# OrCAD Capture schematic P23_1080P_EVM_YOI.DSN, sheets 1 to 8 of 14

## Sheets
1 P10: DLPA2005: size D
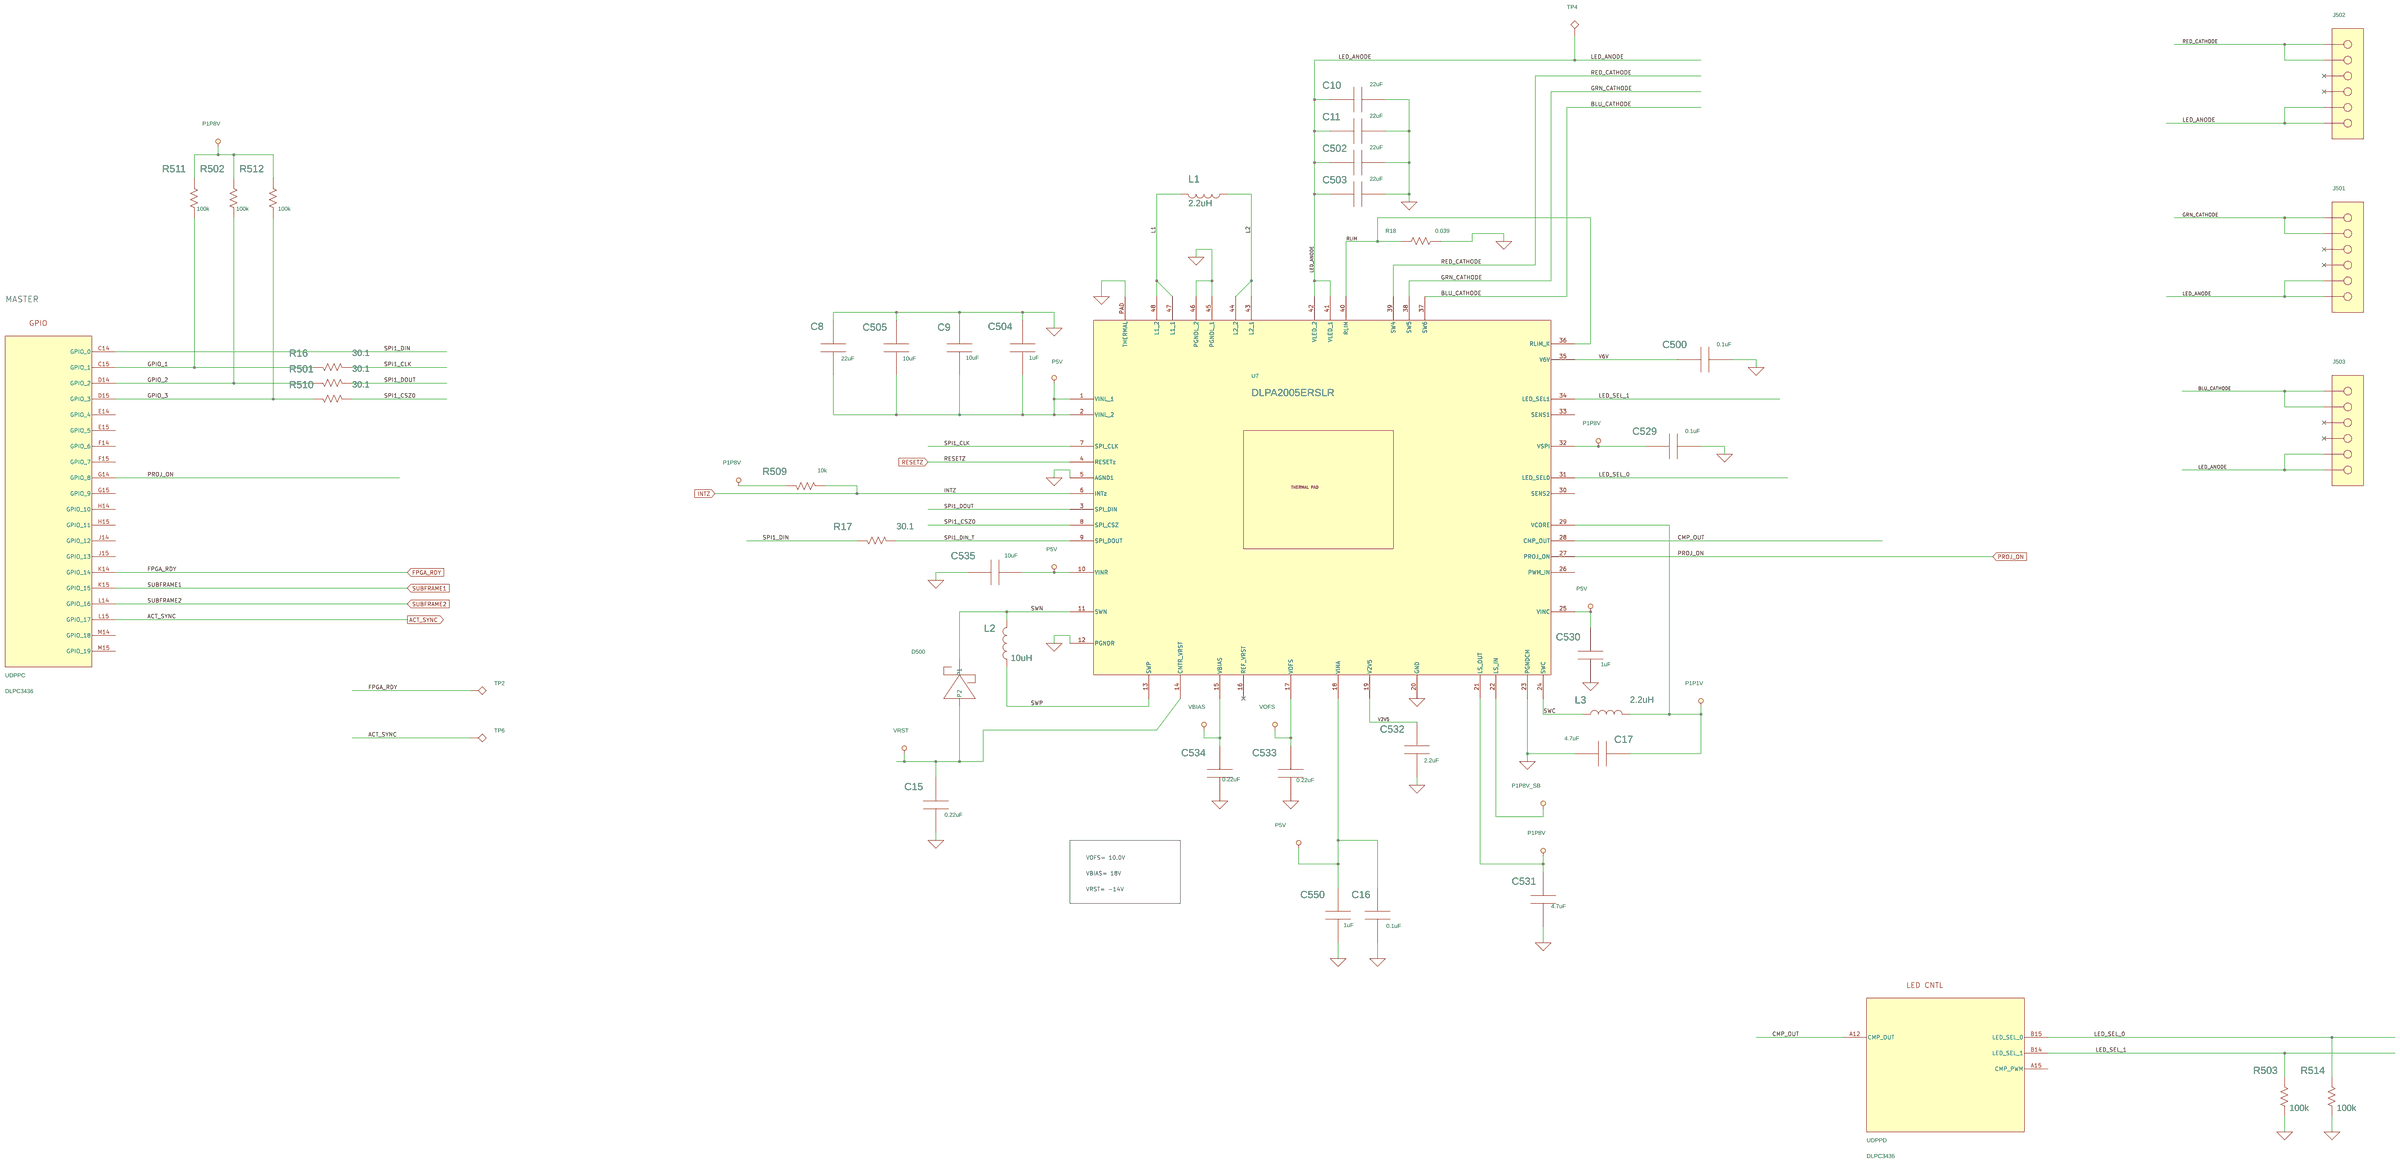
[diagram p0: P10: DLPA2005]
2 P11: Power: size D
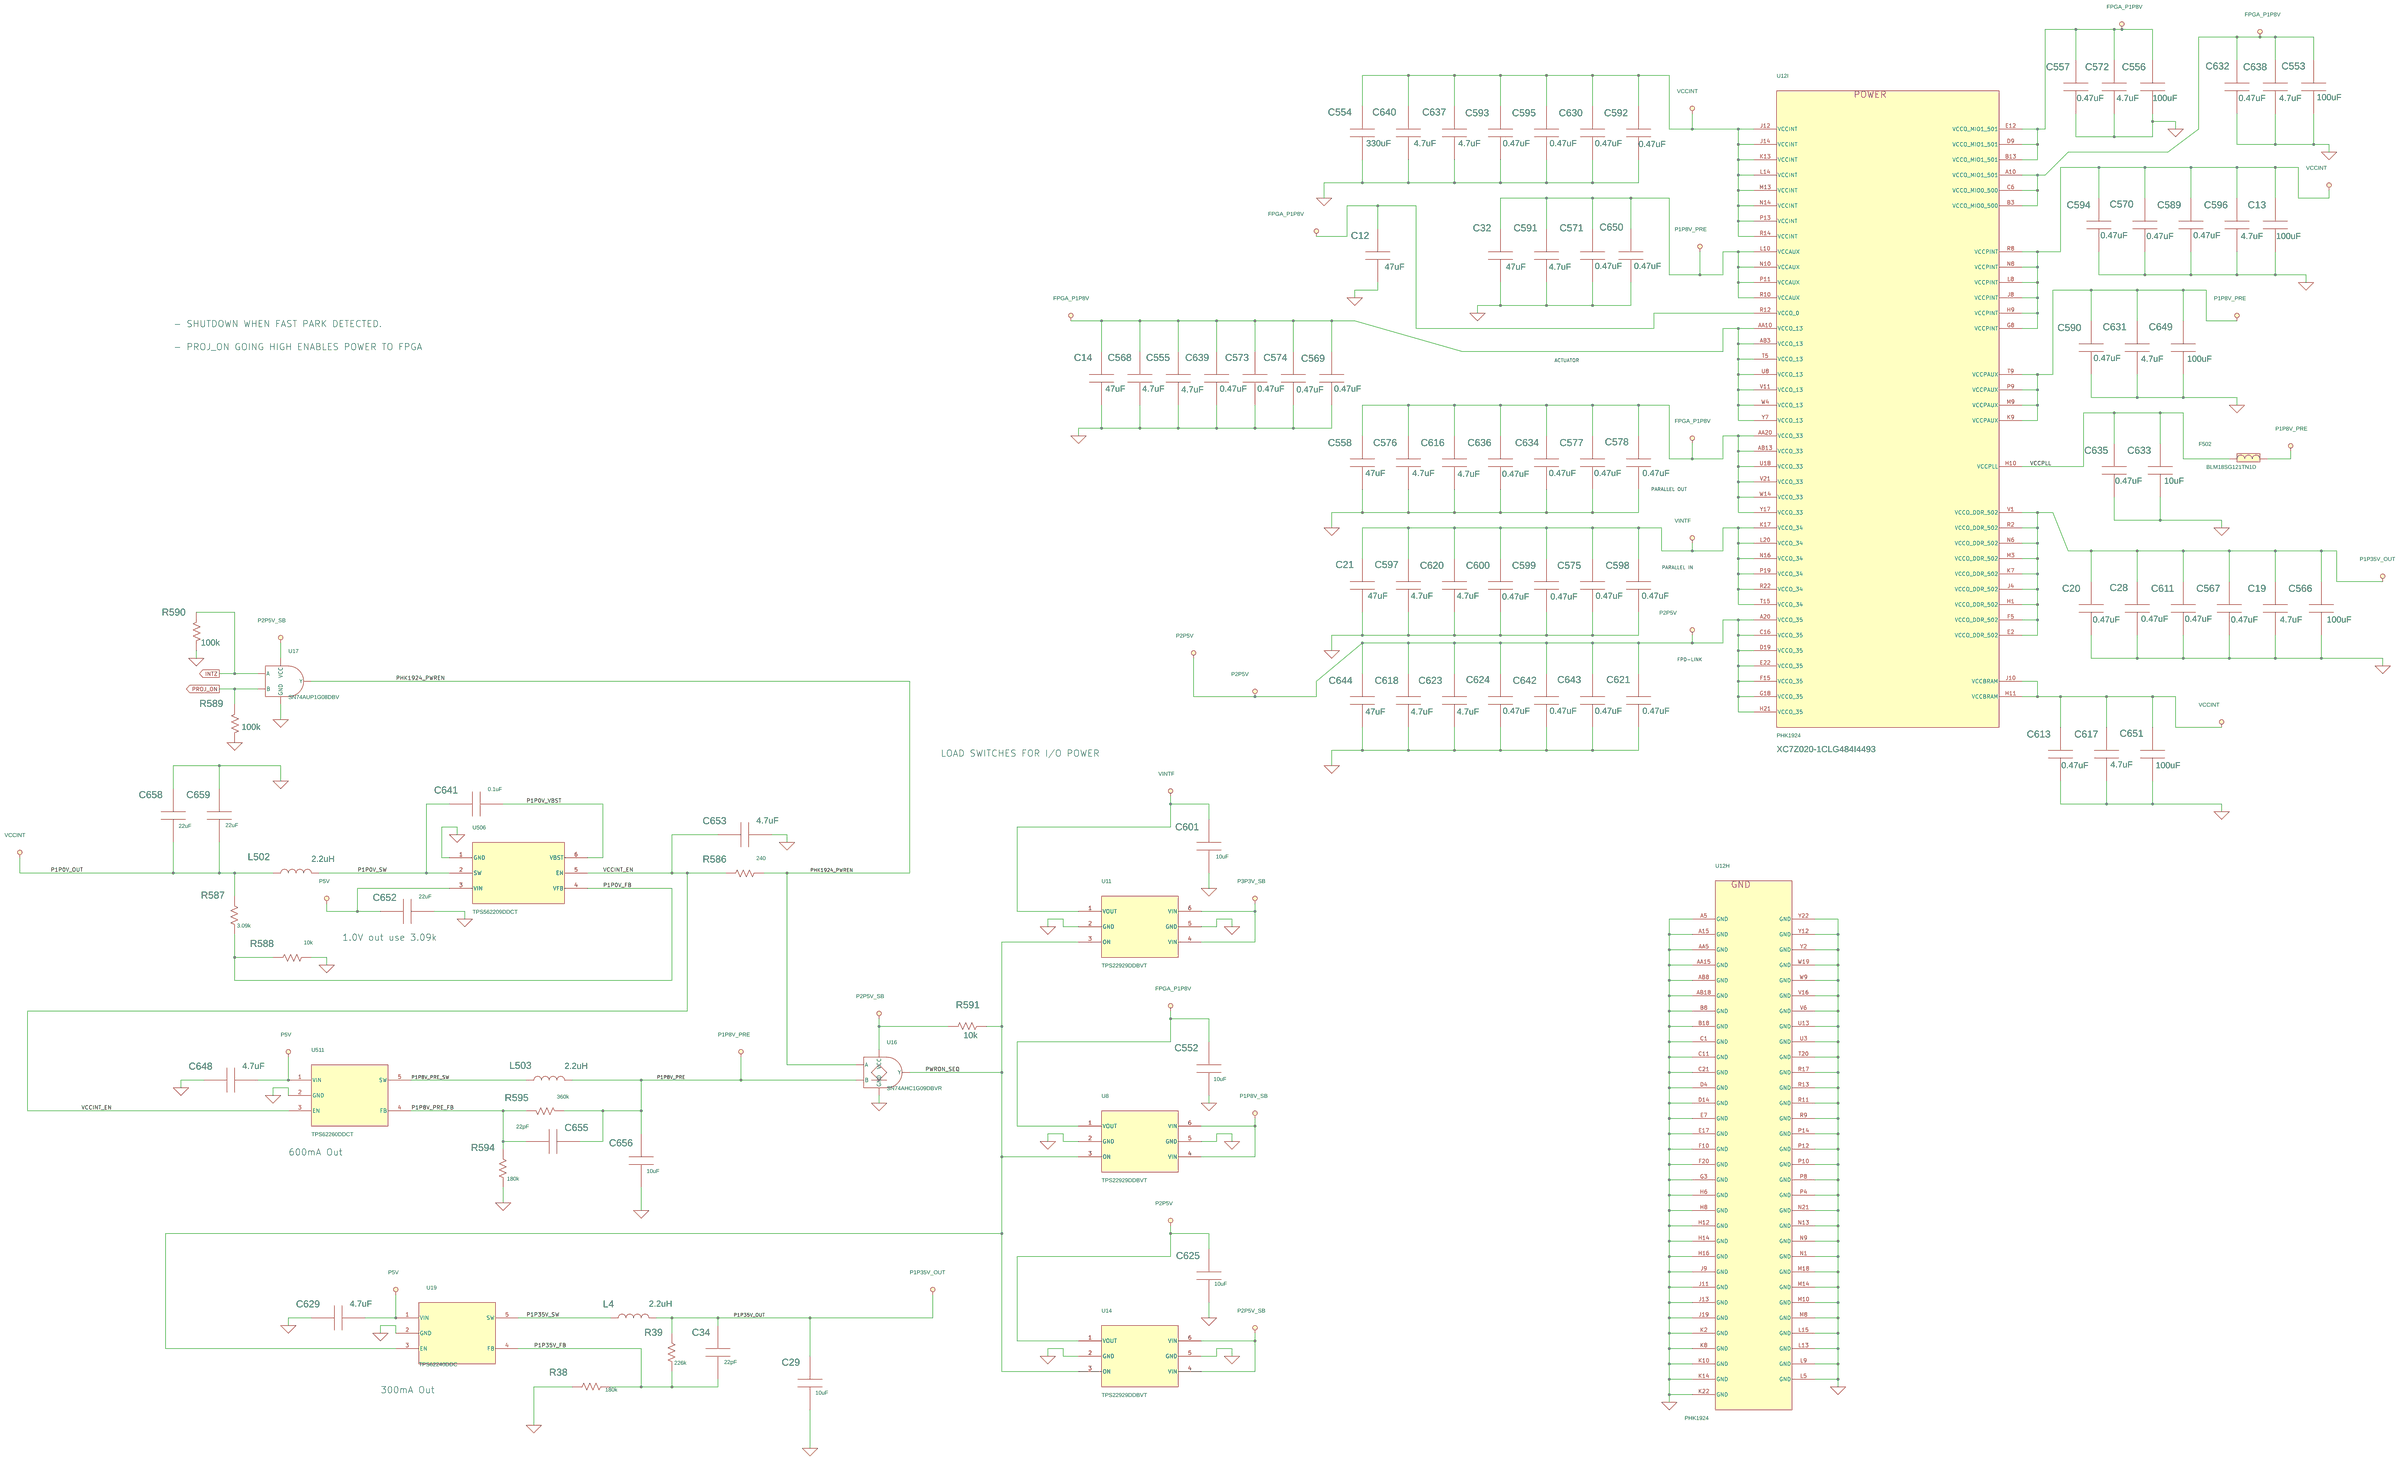
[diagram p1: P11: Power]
3 P14: Disclaimer
4 P03: DLPC3436 & Flash: size D
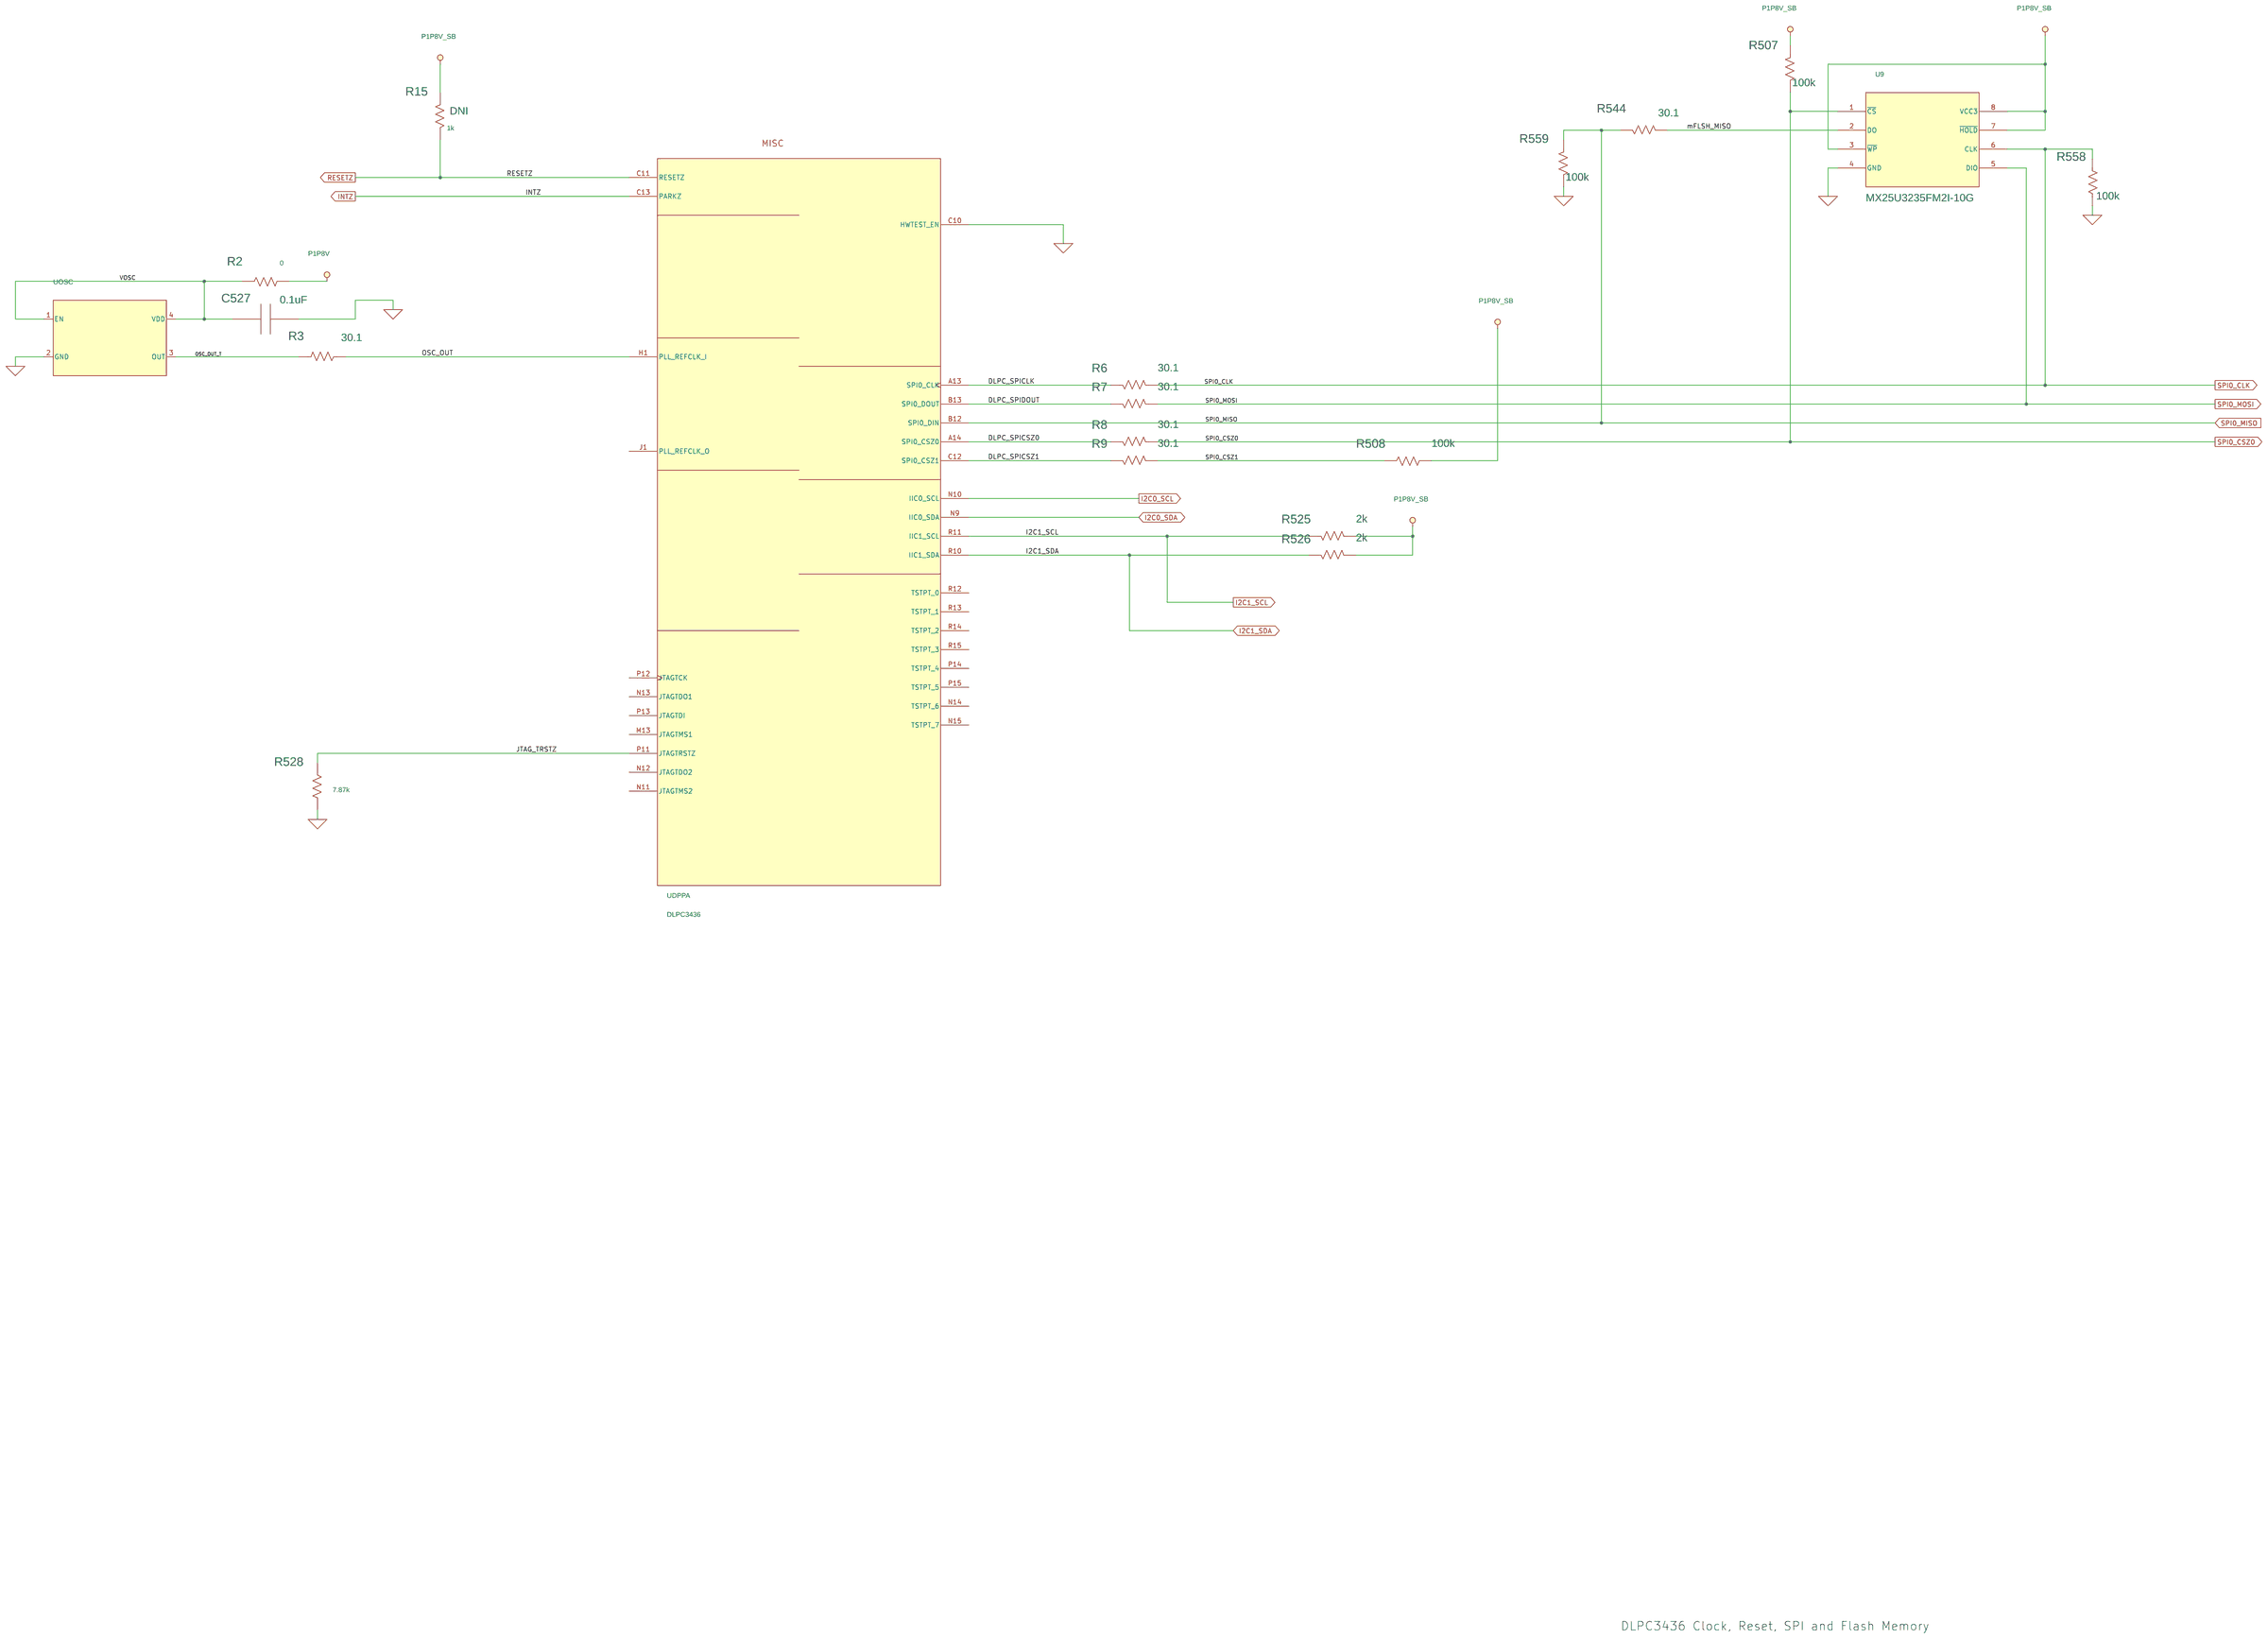
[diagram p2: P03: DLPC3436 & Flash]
5 P01: DLPDLCR230NPEVM: title: TIDA-080009 DLPDLCR230NPEVM; rev: A; company: Texas Instruments Inc.
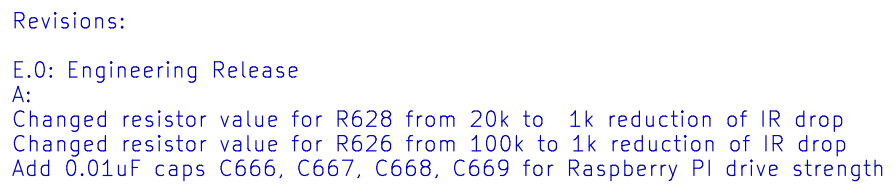
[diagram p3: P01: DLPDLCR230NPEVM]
6 P07: DLPC3436 Power: size D
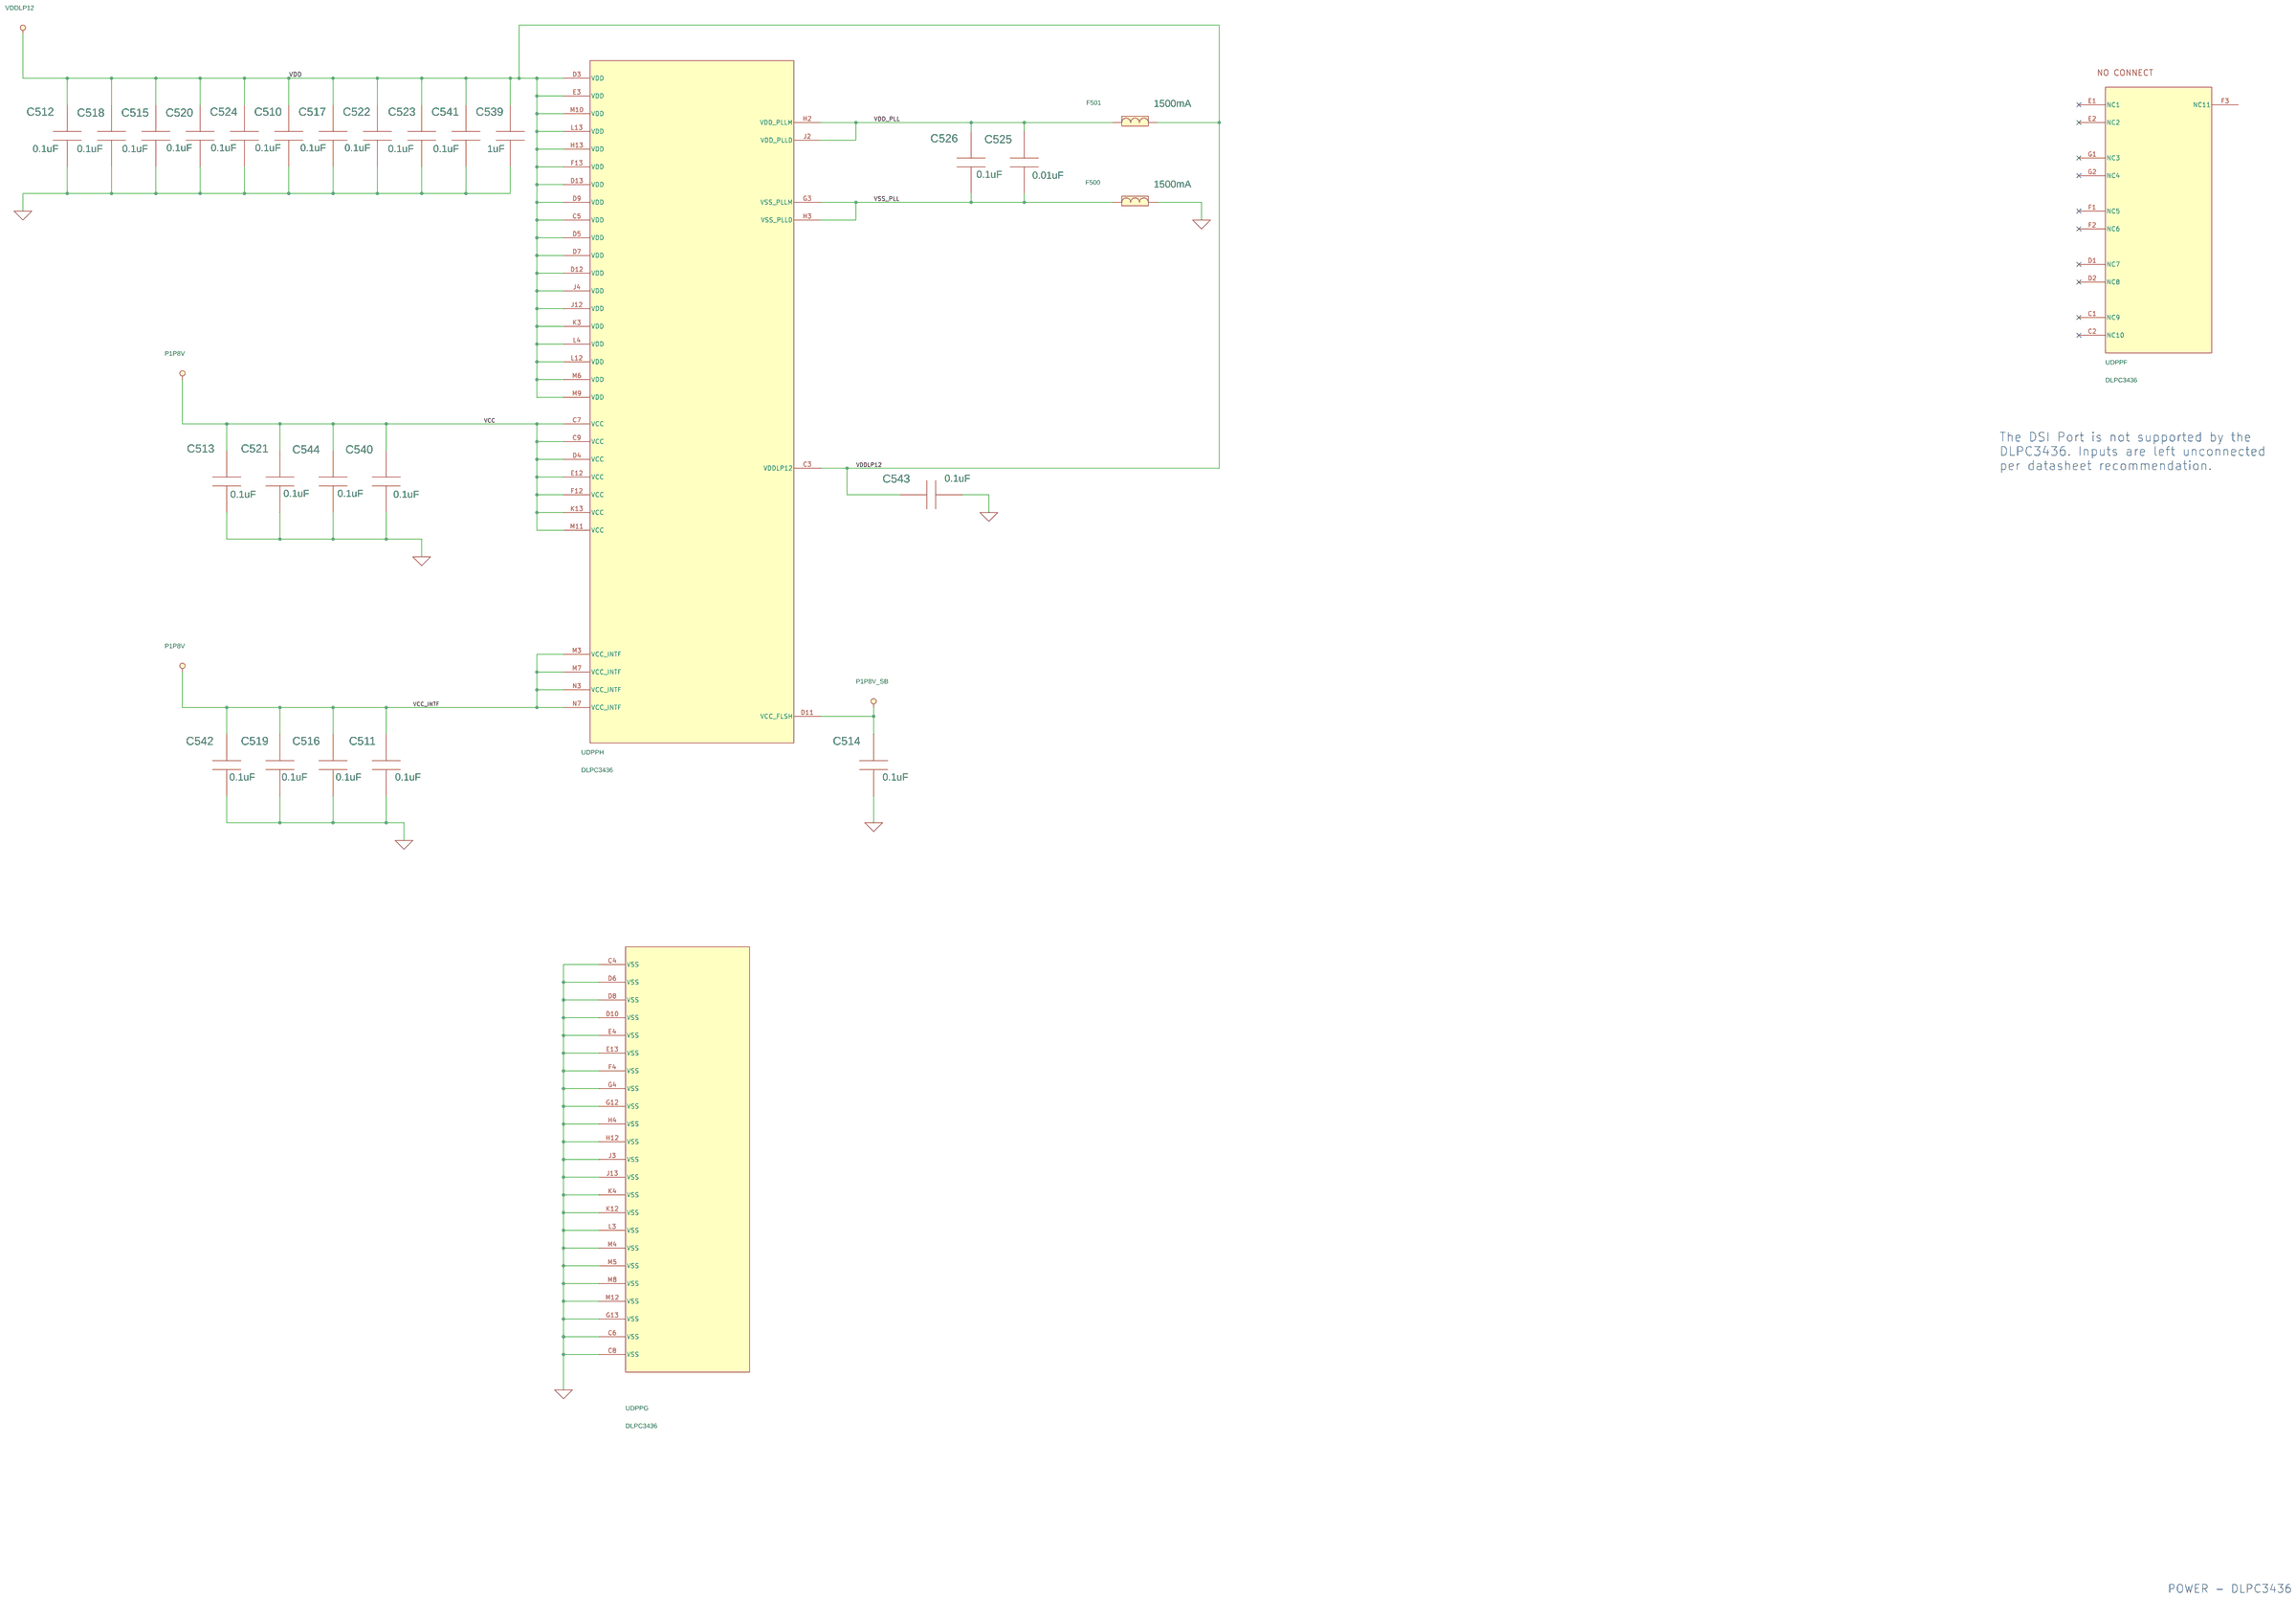
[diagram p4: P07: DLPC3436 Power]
7 P12: Actuator Driver: size D
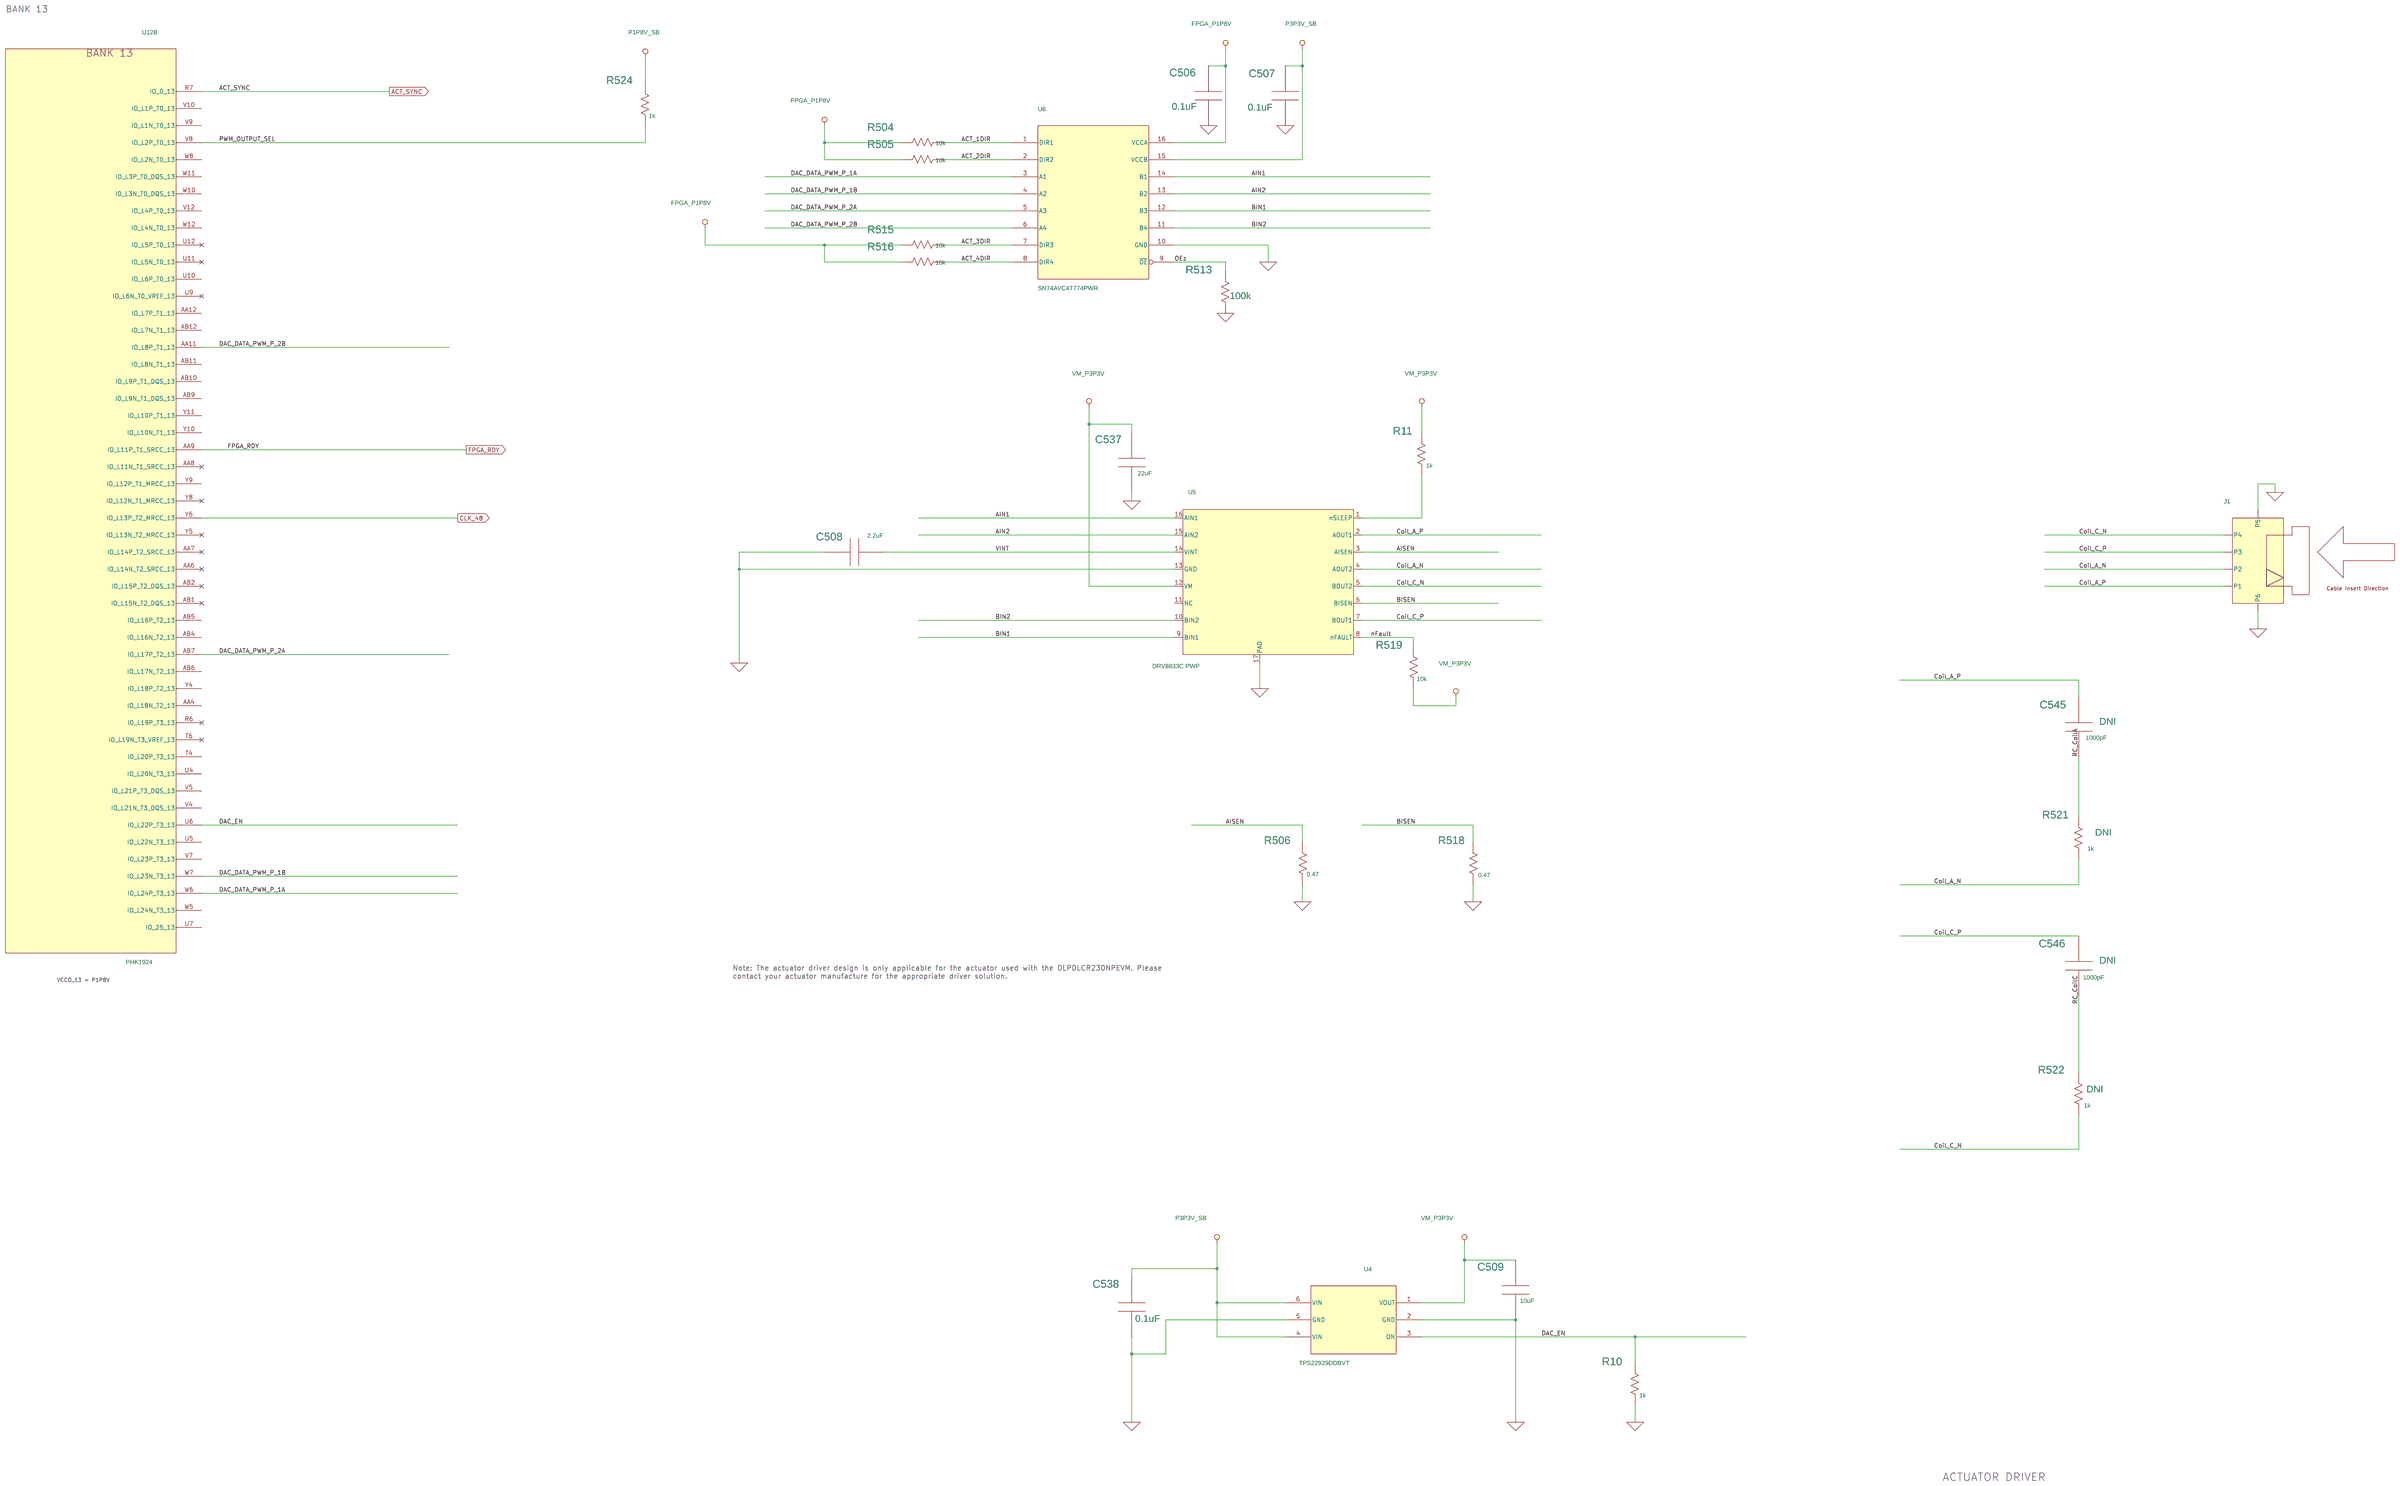
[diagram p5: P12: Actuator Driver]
8 P05: FPD-Link Video Input: size D
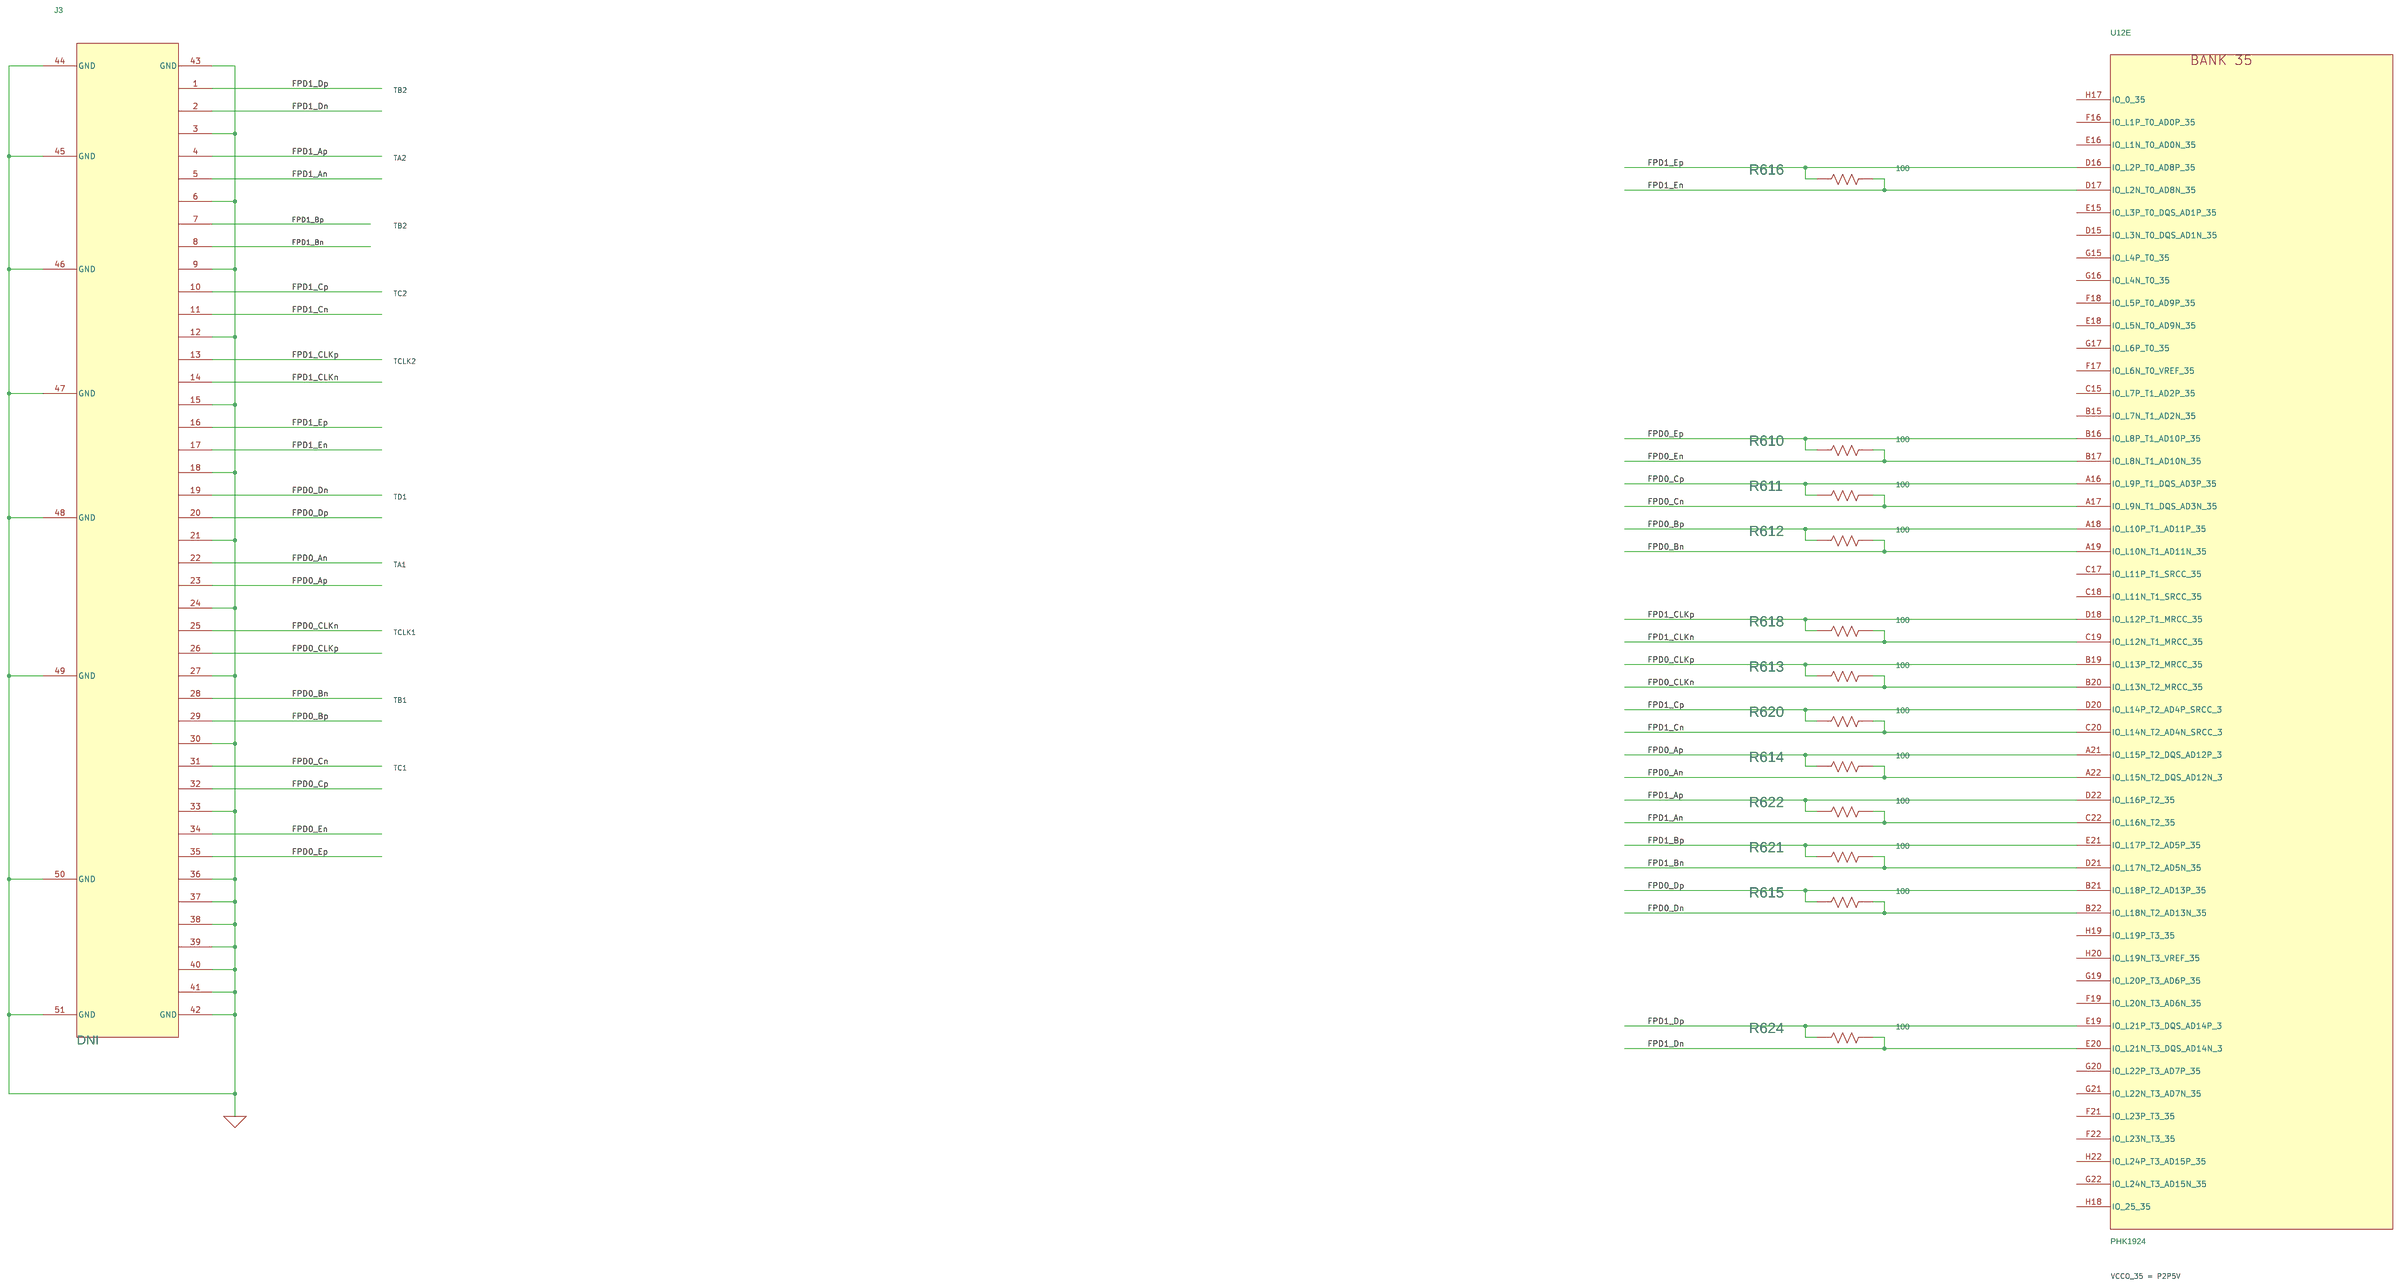
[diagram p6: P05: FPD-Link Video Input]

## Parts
sheet P03: DLPC3436 & Flash
C527  0.1uF  [0402_AVXA]
R2  0  [0402]
R3  30.1  [0402]
R6  30.1  [0402]
R7  30.1  [0402]
R8  30.1  [0402]
R9  30.1  [0402]
R15  1k  [0402]
R507  100k  [0402]
R508  100k  [0402]
R525  2k  [0402]
R526  2k  [0402]
R528  7.87k  [0402]
R544  30.1  [0402]
R558  100k  [0402]
R559  100k  [0402]
U9  MX25U3235FM2I-10G  [SOIC-8_208mil]
UOSC  24MHz  [ECS-2018_2p5mmx2mm]
sheet P05: FPD-Link Video Input
J3  EM,CONN,FI-RE41S-VF  [FI-RE41S-VF_JAE]
R610  100  [0402]
R611  100  [0402]
R612  100  [0402]
R613  100  [0402]
R614  100  [0402]
R615  100  [0402]
R616  100  [0402]
R618  100  [0402]
R620  100  [0402]
R621  100  [0402]
R622  100  [0402]
R624  100  [0402]
sheet P07: DLPC3436 Power
C510  0.1uF  [0402_AVXA]
C511  0.1uF  [0402_AVXA]
C512  0.1uF  [0402_AVXA]
C513  0.1uF  [0402_AVXA]
C514  0.1uF  [0402_AVXA]
C515  0.1uF  [0402_AVXA]
C516  0.1uF  [0402_AVXA]
C517  0.1uF  [0402_AVXA]
C518  0.1uF  [0402_AVXA]
C519  0.1uF  [0402_AVXA]
C520  0.1uF  [0402_AVXA]
C521  0.1uF  [0402_AVXA]
C522  0.1uF  [0402_AVXA]
C523  0.1uF  [0402_AVXA]
C524  0.1uF  [0402_AVXA]
C525  0.01uF  [0402]
C526  0.1uF  [0402_AVXA]
C539  1uF  [0402]
C540  0.1uF  [0402_AVXA]
C541  0.1uF  [0402_AVXA]
C542  0.1uF  [0402_AVXA]
C543  0.1uF  [0402_AVXA]
C544  0.1uF  [0402_AVXA]
F500  BLM15PD800SN1D  [BLM15P]
F501  BLM15PD800SN1D  [BLM15P]
sheet P08: Frame Buffer Memory
U12  PHK1924  [Xilinx_CLG484]  (sections A,B,C,D,E,F,G,H,I,J)
sheet P10: DLPA2005
C8  22uF  [0603]
C9  10uF  [0603]
C10  22uF  [0603]
C11  22uF  [0603]
C15  0.22uF  [0402]
C16  0.1uF  [0402_AVXA]
C17  4.7uF  [0402]
C500  0.1uF  [0402_AVXA]
C502  22uF  [0603]
C503  22uF  [0603]
C504  1uF  [0402]
C505  10uF  [0603]
C529  0.1uF  [0402_AVXA]
C530  1uF  [0402]
C531  4.7uF  [0402]
C532  2.2uF  [0402]
C533  0.22uF  [0402]
C534  0.22uF  [0402]
C535  10uF  [0603]
C550  1uF  [0402]
D500  PMEG4002EL  [SOD882]
J501  SM06B-SRSS-TB(LF)(SN)  [CONN6_SM06B_SH_JST]
J502  SM06B-SRSS-TB(LF)(SN)  [CONN6_SM06B_SH_JST]
J503  SM06B-SRSS-TB(LF)(SN)  [CONN6_SM06B_SH_JST]
L1  2.2uH  [CooperBussmann_DR74]
L2  10uH  [0805]
L3  2.2uH  [1008_2p5mmx2mm]
R16  30.1  [0402]
R17  30.1  [0402]
R18  0.039  [0603]
R501  30.1  [0402]
R502  100k  [0402]
R503  100k  [0402]
R509  10k  [0402]
R510  30.1  [0402]
R511  100k  [0402]
R512  100k  [0402]
R514  100k  [0402]
TP2  TP40  [TP40]
TP4  TP40  [TP40]
TP6  TP40  [TP40]
U7  DLPA2005  [PAD2005_RSL_S-PQFP-N48_QFN48]
UDPP  DLPC3436  [DPP3433_7mmx7mm_VFBGA_176balls]  (sections A,B,C,D,E,F,G,H)
sheet P11: Power
C12  47uF  [0805]
C13  100uF  [0805]
C14  47uF  [0805]
C19  4.7uF  [0402]
C20  0.47uF  [0402]
C21  47uF  [0805]
C28  0.47uF  [0402]
C29  10uF  [0603]
C32  47uF  [0805]
C34  22pF  [0402]
C552  10uF  [0603]
C553  100uF  [0805]
C554  330uF  [1210]
C555  4.7uF  [0402]
C556  100uF  [0805]
C557  0.47uF  [0402]
C558  47uF  [0805]
C566  100uF  [0805]
C567  0.47uF  [0402]
C568  4.7uF  [0402]
C569  0.47uF  [0402]
C570  0.47uF  [0402]
C571  0.47uF  [0402]
C572  4.7uF  [0402]
C573  0.47uF  [0402]
C574  0.47uF  [0402]
C575  0.47uF  [0402]
C576  4.7uF  [0402]
C577  0.47uF  [0402]
C578  0.47uF  [0402]
C589  0.47uF  [0402]
C590  0.47uF  [0402]
C591  4.7uF  [0402]
C592  0.47uF  [0402]
C593  0.47uF  [0402]
C594  0.47uF  [0402]
C595  0.47uF  [0402]
C596  4.7uF  [0402]
C597  4.7uF  [0402]
C598  0.47uF  [0402]
C599  0.47uF  [0402]
C600  0.47uF  [0402]
C601  10uF  [0603]
C611  0.47uF  [0402]
C613  0.47uF  [0402]
C616  4.7uF  [0402]
C617  4.7uF  [0402]
C618  4.7uF  [0402]
C620  4.7uF  [0402]
C621  0.47uF  [0402]
C623  4.7uF  [0402]
C624  0.47uF  [0402]
C625  10uF  [0603]
C629  4.7uF  [0402]
C630  0.47uF  [0402]
C631  4.7uF  [0402]
C632  0.47uF  [0402]
C633  10uF  [0603]
C634  0.47uF  [0402]
C635  0.47uF  [0402]
C636  0.47uF  [0402]
C637  4.7uF  [0402]
C638  4.7uF  [0402]
C639  0.47uF  [0402]
C640  4.7uF  [0402]
C641  0.1uF  [0402_AVXA]
C642  0.47uF  [0402]
C643  0.47uF  [0402]
C644  47uF  [0805]
C648  4.7uF  [0402]
C649  100uF  [0805]
C650  0.47uF  [0402]
C651  100uF  [0805]
C652  22uF  [0603]
C653  4.7uF  [0402]
C655  22pF  [0402]
C656  10uF  [0603]
C658  22uF  [0603]
C659  22uF  [0603]
F502  BLM18SG121TN1D  [0603]
L4  2.2uH  [1008_2p5mmx2mm]
L502  2.2uH  [XFL4020-Series]
L503  2.2uH  [1008_2p5mmx2mm]
R38  180k  [0402]
R39  226k  [0402]
R586  240  [0402]
R587  3.09k  [0402]
R588  10k  [0402]
R589  100k  [0402]
R590  100k  [0402]
R591  10k  [0402]
R594  180k  [0402]
R595  360k  [0402]
U8  TPS22929DDBVT  [SOT23-6_DBV_R-PDSO-G6]
U11  TPS22929DDBVT  [SOT23-6_DBV_R-PDSO-G6]
U14  TPS22929DDBVT  [SOT23-6_DBV_R-PDSO-G6]
U16  SN74AHC1G09DBVR  [SC70_DBV_R-PDSO-G5]
U17  SN74AUP1G08DBV  [SC70_DBV_R-PDSO-G5]
U19  TPS62240DDC  [TSOT-23_DDC_R-PDSO-G5]
U506  TPS562209DDCT  [SOT-23_DDC_R-PDSO-G6]
U511  TPS62260DDCT  [TSOT-23_DDC_R-PDSO-G5]
sheet P12: Actuator Driver
C506  0.1uF  [0402_AVXA]
C507  0.1uF  [0402_AVXA]
C508  2.2uF  [0402]
C509  10uF  [0603]
C537  22uF  [0603]
C538  0.1uF  [0402_AVXA]
C545  1000pF  [0603]
C546  1000pF  [0603]
J1  5034800400  [Molex_5034800400_2GPADS]
R10  1k  [0402]
R11  1k  [0402]
R504  10k  [0402]
R505  10k  [0402]
R506  0.47  [0603]
R513  100k  [0402]
R515  10k  [0402]
R516  10k  [0402]
R518  0.47  [0603]
R519  10k  [0402]
R521  1k  [0402]
R522  1k  [0402]
R524  1k  [0402]
U4  TPS22929DDBVT  [SOT23-6_DBV_R-PDSO-G6]
U5  DRV8833C PWP  [16-HTSSOP]
U6  SN74AVC4T774PWR  [TSSOP16_PW]

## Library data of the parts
C506 C507 C510-C524 C526 C527 C538 C540-C544 C641 = PAS,CAP,NP,large: DigiKey: 490-7998-1-ND; DigiReel: 490-7998-6-ND; Family: passive; Lead Style: SMT; MFG: Murata; Material: x7r; P/D_NUM: GCM155R71C104KA55J; Part Number: GCM155R71C104KA55J; Part Specific: CAP CER .1UF 16V X7R 0402; TOLERANCE: 10%; Type: capacitor; VENDOR: Murata; VPC: 16V
R2 = PAS,R,large: DigiKey: P0.0JCT-ND; DigiReel: P0.0JDKR-ND; Family: passive; Index PN: 687; Lead Style: SMT; MFG: Panasonic; Material: chip; P/D_NUM: ERJ-2GE0R00X; Part Number: ERJ-2GE0R00X; Part Specific: RES 0.0 OHM 1/16W 0402 SMD; Power: 1/16W; Type: resistor; VENDOR: Panasonic; VPC: 1/16W
R3 R6-R9 R16 R17 R501 R510 R544 = PAS,R,large: DigiKey: YAG3111CT-ND; DigiReel: P30.1LDKR-ND; Family: passive; Index PN: 976; Lead Style: SMT; MFG: Yageo; Material: chip; P/D_NUM: RC0402FR-0730R1L; Part Number: RC0402FR-0730R1L; Part Specific: RES 30.1 OHM 1/16W 1% 0402 SMD; Power: 1/16W; TOLERANCE: 1%; Type: resistor; VENDOR: Yageo; VPC: 1/16W
R15 = PAS,R,large: DigiKey: 311-1.00KLRCT-ND; DigiReel: P1.00KLDKR-ND; Family: passive; Index PN: 684; Install: DNI; Lead Style: SMT; MFG: Yageo; Material: chip; P/D_NUM: RC0402FR-071KL; Part Number: RC0402FR-071KL; Part Specific: RES 1.00K OHM 1/10W 1% 0402 SMD; Power: 1/16W; TOLERANCE: 1%; Type: resistor; VENDOR: Yageo; VPC: 1/16W
R502 R503 R507 R508 R511-R514 R558 R559 = PAS,R,large: DigiKey: 541-100KLCT-ND; DigiReel: 541-100KLDKR-ND; Family: passive; Index PN: 712; Lead Style: SMT; MFG: Vishay/Dale; Material: chip; P/D_NUM: CRCW0402100KFKED; Part Number: CRCW0402100KFKED; Part Specific: RES 100K OHM 1/10W 1% 0402 SMD; Power: 1/16W; TOLERANCE: 1%; Type: resistor; VENDOR: Vishay/Dale; VPC: 1/16W
R525 R526 = PAS,R,large: DigiKey: P2.00KLCT-ND; DigiReel: P2.00KLDKR-ND; Family: passive; Index PN: 1348; Lead Style: SMT; MFG: Panasonic; P/D_NUM: ERJ-2RKF2001X; Part Number: ERJ-2RKF2001X; Part Specific: RES SMD 2K OHM 1% 1/10W 0402; Power: 1%; Type: resistor; VENDOR: Panasonic; VPC: 1/16W
R528 = PAS,R,large: DigiKey: P7.87KLCT-ND; DigiReel: P7.87KLDKR-ND; Family: passive; Index PN: 1175; Lead Style: SMT; MFG: Panasonic; Material: chip; P/D_NUM: ERJ-2RKF7871X; Part Number: ERJ-2RKF7871X; Part Specific: RES 7.87K OHM 1/10W 1% 0402 SMD; Type: resistor; VENDOR: Panasonic; VPC: 1/10W
U9 = MEM,FLASH,SERIAL,W25XxxALxNIG: DigiKey: 1092-1137-ND; DigiReel: ---; Family: memory; Install: Y; Lead Style: SMT; MFG: Macronix; Part Specific: IC FLASH 32MBIT 104MHZ 8SOIC; Type: flash, spi; VENDOR: Macronix; VPC: 1.65-1.95V
UOSC = ANA,OSC,4P,2X: DigiKey: 535-11728-1-ND; DigiReel: 535-11728-6-ND; Family: analog; Install: Y; Lead Style: SMT; MFG: Abracon; P/D_NUM: ASDMB-24.000MHZ-LC-T; Part Number: ASDMB-24.000MHZ-LC-T; Part Specific: OSC MEMS 24.000MHZ CMOS SMD 1.8V-3.3V; Type: oscillator; VPC: 1.8V-3.3V; Vendor: Abracon
J3 = EM,CONN,FI-RE41S-VF_9: Install: DNI; MFG: JAE Electronics; P/D_NUM: FI-RE41S-VF-R1300; Part Number: FI-RE41S-VF-R1300; Part Specific: CONN RCPT 41POS 0.02 GOLD SMD; Type: connector; Vendor: JAE
R610-R616 R618 R620-R622 R624 = PAS,R,large: DigiKey: P100LCT-ND; DigiReel: P100LDKR-ND; Family: passive; Index PN: 690; Lead Style: SMT; MFG: Panasonic; Material: chip; P/D_NUM: ERJ-2RKF1000X; Part Number: ERJ-2RKF1000X; Part Specific: RES 100 OHM 1/10W 1% 0402 SMD; Power: 1/16W; TOLERANCE: 1%; Type: resistor; VENDOR: Panasonic; VPC: 1/16W
C525 = PAS,CAP,NP,large: DigiKey: 399-1038-1-ND; DigiReel: 399-1038-6-ND; Family: passive; Lead Style: SMT; MFG: KEMET; Material: x7r; P/D_NUM: C0402C103K4RACTU; Part Number: C0402C103K4RACTU; Part Specific: CAP CER 10000PF 16V X7R 0402; TOLERANCE: 10%; Type: capacitor; VENDOR: KEMET; VPC: 16V
C539 = PAS,CAP,NP,large: DigiKey: 587-3245-1-ND; DigiReel: 587-3245-6-ND; Family: passive; Lead Style: SMT; MFG: Taiyo Yuden; Material: x5r; P/D_NUM: TMK105BJ105MV-F; Part Number: TMK105BJ105MV-F; Part Specific: CAP CER 1.0UF 25V X5R 0402; TOLERANCE: 20%; Type: capacitor; VENDOR: Taiyo Yuden; VPC: 25V; Voltage: 25V
F500 F501 = PAS,FERRITE_BEAD,3: DigiKey: 490-5202-1-ND; DigiReel: 490-5202-6-ND; Family: passive; Index PN: 999; Install: Y; Lead Style: SMT; MFG: Murata; Part Specific: FERRITE CHIP 80 OHM 1500MA 0402; Type: ferrite bead; VENDOR: Murata; VPC: 1500mA
U12 = TIDLP,XPR_FPGA,Zynq-7020new: DigiKey: ---; DigiReel: ---; Family: processor; Index PN: 1304; Lead Style: SMT; MFG: Xilinx; P/D_NUM: XC7Z020-1CLG484I4493; Part Number: XC7Z020-1CLG484I4493; Part Specific: Xilinx FPGA XC7Z020-1CLG484I; Type: dlp; Vendor: Xilinx
C8 = PAS,CAP,NP,large_2: DigiKey: 445-9077-1-ND; DigiReel: 445-9077-6-ND; Family: passive; Lead Style: SMT; MFG: Samsung; Material: x5r; P/D_NUM: C1608X5R1A226M080AC; Part Number: C1608X5R1A226M080AC; Part Specific: CAP CER 22UF 10V X5R 0603; TOLERANCE: 20%; Type: capacitor; VENDOR: TDK; VPC: 10V; Voltage: 10V
C9 C505 C535 = PAS,CAP,NP,large_2: DigiKey: 445-6853-1-ND; DigiReel: 445-6853-6-ND; Family: passive; Index PN: 1207; Lead Style: SMT; MFG: TDK; P/D_NUM: C1608X5R1A106M080AC; Part Number: C1608X5R1A106M080AC; Part Specific: CAP CER 10UF 10V 20% X5R 0603; TOLERANCE: 20%; Type: capacitor; VENDOR: TDK; VPC: 10V; Voltage: 6.3V
C10 C11 C502 C503 C652 = PAS,CAP,NP,large_2: DigiKey: 445-9077-1-ND; DigiReel: 445-9077-6-ND; Family: passive; Lead Style: SMT; MFG: TDK; Material: x5r; P/D_NUM: C1608X5R1A226M080AC; Part Number: C1608X5R1A226M080AC; Part Specific: CAP CER 22UF 10V X5R 0603; TOLERANCE: 20%; Type: capacitor; VENDOR: TDK; VPC: 10V; Voltage: 10V
C15 C533 C534 = PAS,CAP,NP,large_2: DigiKey: 490-12265-1-ND; DigiReel: 490-12265-6-ND; Family: passive; Lead Style: SMT; MFG: Murata; Material: x5r; P/D_NUM: GRT155R61E224KE01D; Part Number: GRT155R61E224KE01D; Part Specific: CAP CER 0.22UF 25V 10% X5R 0402; TOLERANCE: 10%; Type: capacitor; VENDOR: Murata; VPC: 25V; Voltage: 25V
C16 C500 C529 = PAS,CAP,NP,large_2: DigiKey: 490-7998-1-ND; DigiReel: 490-7998-6-ND; Family: passive; Lead Style: SMT; MFG: Murata; Material: x7r; P/D_NUM: GCM155R71C104KA55J; Part Number: GCM155R71C104KA55J; Part Specific: CAP CER .1UF 16V X7R 0402; TOLERANCE: 10%; Type: capacitor; VENDOR: Murata; VPC: 16V
C17 C531 = PAS,CAP,NP,large_2: DigiKey: 445-7395-1-ND; DigiReel: 445-7395-6-ND; Family: passive; Lead Style: SMT; MFG: TDK; Material: x5r; P/D_NUM: C1005X5R0J475M050BC; Part Number: C1005X5R0J475M050BC; Part Specific: CAP CER 4.7UF 6.3V 20% X5R 0402; TOLERANCE: 20%; Type: capacitor; VENDOR: TDK; VPC: 6.3V
C504 C530 C550 = PAS,CAP,NP,large_2: DigiKey: 587-3245-1-ND; DigiReel: 587-3245-6-ND; Family: passive; Lead Style: SMT; MFG: Taiyo Yuden; Material: x5r; P/D_NUM: TMK105BJ105MV-F; Part Number: TMK105BJ105MV-F; Part Specific: CAP CER 1.0UF 25V X5R 0402; TOLERANCE: 20%; Type: capacitor; VENDOR: Taiyo Yuden; VPC: 25V; Voltage: 25V
C532 = PAS,CAP,NP,large_2: DigiKey: 445-4999-1-ND; DigiReel: 445-4999-6-ND; Family: passive; Index PN: 915; Lead Style: SMT; MFG: TDK; Material: x5r; P/D_NUM: C1005X5R0J225M050BC; Part Number: C1005X5R0J225M050BC; Part Specific: CAP CER 2.2UF 6.3V X5R 0402; TOLERANCE: 10%; Type: capacitor; VENDOR: TDK; VPC: 6.3V; Voltage: 25V
D500 = PAS,DIODE,SCHOTTKY,large: DigiKey: 568-4131-1-ND; DigiReel: 568-4131-6-ND; Family: passive; Index PN: 907; Lead Style: SMT; MFG: NXP Semiconductors; P/D_NUM: PMEG4002EL,315; Part Number: PMEG4002EL,315; Part Specific: SCHOTTKY RECT 40V 0.2A SOD882; Type: diode,schottky; VENDOR: NXP Semiconductors; VPC: 40V; Voltage: 40V
J501-J503 = EM,HDR,6P,1R,2X: DigiKey: 455-1806-1-ND; DigiReel: 455-1806-2-ND; Family: electro/mechanical; Lead Style: SMT; MFG: JST Sales America Inc.; Part Specific: CONN HEADER SMD R/A 6POS 1MM; Pin Cnt: 6; Pin Spacing: 1 mm; Row Cnt: 1; Type: header; Vendor: JST
L1 = PAS,INDUCTOR,_large: DigiKey: 513-1140-1-ND; DigiReel: 513-1140-6-ND; Family: passive; Lead Style: SMT; MFG: Eaton - Electronics Division; P/D_NUM: DR74-2R2-R; Part Number: DR74-2R2-R; Part Specific: INDUCTOR SHIELD PWR 2.2UH SMD Irms-4.76A Isat-7.06A; Tolerance: 20%; Type: inductor; VENDOR: Eaton - Electronics Division; VPC: 4.76A
L2 = PAS,INDUCTOR,_large: DigiKey: 587-1632-1-ND; DigiReel: 587-1632-6-ND; Family: passive; Index PN: 901; Lead Style: SMT; MFG: Taiyo Yuden; P/D_NUM: CBL2012T100M; Part Number: CBL2012T100M; Part Specific: INDUCTOR 10UH 20% 0805 SMD; Type: inductor; VENDOR: Taiyo Yuden
L3 = PAS,INDUCTOR,_large: DigiKey: 490-5114-1-ND; DigiReel: 490-5114-6-ND; Family: passive; Index PN: 1149; Lead Style: SMT; MFG: Murata; P/D_NUM: LQM2HPN2R2MG0L; Part Number: LQM2HPN2R2MG0L; Part Specific: INDUCTOR 2.2UH 20% 1300MA 1008; Type: inductor; VENDOR: Murata
R18 = PAS,R,large: DigiKey: RHM1271CT-ND; DigiReel: RHM1271DKR-ND; Family: passive; Index PN: 254; Lead Style: SMT; MFG: Rohm; Material: chip; P/D_NUM: UCR03EWPFSR039; Part Number: UCR03EWPFSR039; Part Specific: RES 0.039 OHM 1/4W 1% 0603; Tolerance: 1%; Type: resistor; VPC: 1/4W; Vendor: Rohm
R504 R505 R509 R515 R516 R519 R588 = PAS,R,large: DigiKey: P10.0KLCT-ND; DigiReel: P10.0KLDKR-ND; Family: passive; Index PN: 680; Lead Style: SMT; MFG: Panasonic; Material: chip; P/D_NUM: ERJ-2RKF1002X; Part Number: ERJ-2RKF1002X; Part Specific: RES SMD 10K OHM 1% 1/10W 0402; Power: 1/16W; TOLERANCE: 1%; Type: resistor; VENDOR: Panasonic; VPC: 1/16W
TP2 TP4 TP6 = EM,TERM,TESTPOINT: DigiKey: ---; DigiReel: ---; Family: board feature; Index PN: 995; Install: DNI; MFG: -- NOT A PART --; Type: hole,plated; Vendor: -- NOT A PART --
U7 = TIDLP,PAD2005,_C3: DigiKey: ---; DigiReel: ---; Family: power; Index PN: 1201; Lead Style: SMT; MFG: Texas Instruments; P/D_NUM: DLPA2005ERSLR; Part Number: DLPA2005ERSLR; Part Specific: Power & LED Driver IC for DLP PICO Projector; Pin Spacing: 0.4mm; Type: regulator; Vendor: Texas Instruments
UDPP = TIDLP,DPP3430,_no_DSI: DigiKey: ---; DigiReel: ---; Family: processor; Lead Style: SMT; MFG: Texas Instruments; Mouser: ---; P/D_NUM: DLPC3436CZVBR; Part Number: DLPC3436CZVBR; Part Specific: DLP-PICO Processor; Type: dlp; Vendor: Texas Instruments; Install: Y
C12 C14 C21 C32 C558 C644 = PAS,CAP,NP,large: DigiKey: 490-9961-1-ND; DigiReel: 490-9961-6-ND; Family: passive; Index PN: 1350; Lead Style: SMT; MFG: Murata; P/D_NUM: GRM21BR61A476ME15L; Part Number: GRM21BR61A476ME15L; Part Specific: 47µF ±20% 10V X5R Ceramic Capacitor -55°C ~ 85°C; TOLERANCE: 20%; Type: capacitor; VENDOR: Murata; VPC: 10V
C13 C553 C556 C566 C649 C651 = PAS,CAP,NP,large: DigiKey: 490-10510-1-ND; DigiReel: 490-10510-6-ND; Family: passive; Index PN: 1352; Lead Style: SMT; MFG: Murata; P/D_NUM: GRM21BR60G107ME15L; Part Number: GRM21BR60G107ME15L; Part Specific: 100µF ±20% 4V X5R Ceramic Capacitor -55°C ~ 85°C; TOLERANCE: 20%; Type: capacitor; VENDOR: Murata; VPC: 4V
C19 C555 C568 C572 C576 C591 C596 C597 C616-C618 C620 C623 C629 C631 C637 C638 C640 C648 C653 = PAS,CAP,NP,large: DigiKey: 445-7395-1-ND; DigiReel: 445-7395-6-ND; Family: passive; Lead Style: SMT; MFG: TDK; Material: x5r; P/D_NUM: C1005X5R0J475M050BC; Part Number: C1005X5R0J475M050BC; Part Specific: CAP CER 4.7UF 6.3V 20% X5R 0402; TOLERANCE: 20%; Type: capacitor; VENDOR: TDK; VPC: 6.3V
C20 C28 C557 C567 C569-C571 C573-C575 C577 C578 C589 C590 C592-C595 C598-C600 C611 C613 C621 C624 C630 C632 C634-C636 C639 C642 C643 C650 = PAS,CAP,NP,large: DigiKey: 490-12269-1-ND; DigiReel: 490-12269-6-ND; Family: passive; Lead Style: SMT; MFG: Murata; P/D_NUM: GRT155R61E474KE01D; Part Number: GRT155R61E474KE01D; Part Specific: CAP CER 0.47UF 25V X5R 0402; TOLERANCE: 10%; Type: capacitor; VENDOR: Murata; VPC: 25V
C29 C509 C552 C601 C625 C633 C656 = PAS,CAP,NP,large: DigiKey: 445-4112-1-ND; DigiReel: 445-4112-6-ND; Family: passive; Index PN: 906; Lead Style: SMT; MFG: TDK; Material: x5r; P/D_NUM: C1608X5R0J106M080AB; Part Number: C1608X5R0J106M080AB; Part Specific: CAP CERAMIC 10UF 6.3V X5R 0603; TOLERANCE: 20%; Type: capacitor; VENDOR: TDK; VPC: 6.3V
C34 C655 = PAS,CAP,NP,large: DigiKey: 490-17747-1-ND; DigiReel: 490-17747-6-ND; Family: passive; Lead Style: SMT; MFG: Murata; Material: npo; P/D_NUM: GCM1555C1H220JA16J; Part Number: GCM1555C1H220JA16J; Part Specific: CAP CER 22PF 50V NP0 0402; TOLERANCE: 5%; Type: capacitor; VENDOR: Murata; VPC: 50V
C554 = PAS,CAP,NP,large: DigiKey: 490-13976-1-ND; DigiReel: 490-13976-6-ND; Family: passive; Index PN: 1351; Lead Style: SMT; MFG: Murata; P/D_NUM: GRM32ER60G337ME05L; Part Number: GRM32ER60G337ME05L; Part Specific: 330µF ±20% 4V X5R Ceramic Capacitor -55°C ~ 85°C; TOLERANCE: 20%; Type: capacitor; VENDOR: Murata; VPC: 4V
C537 C658 C659 = PAS,CAP,NP,large: DigiKey: 445-9077-1-ND; DigiReel: 445-9077-6-ND; Family: passive; Index PN: 1203; Lead Style: SMT; MFG: TDK; Material: x5r; P/D_NUM: C1608X5R1A226M080AC; Part Number: C1608X5R1A226M080AC; Part Specific: CAP CER 22UF 10V 20% X5R 0603; TOLERANCE: 20%; Type: capacitor; VENDOR: TDK; VPC: 10V
F502 = PAS,FERRITE_BEAD,3: DigiKey: 490-3996-1-ND; DigiReel: 490-3996-6-ND; Family: passive; Index PN: 1312; Install: Y; Lead Style: SMT; MFG: Murata; Part Specific: FERRITE BEAD 120 OHM 0603; Type: ferrite bead; VENDOR: Murata; VPC: 3A
L4 L503 = PAS,INDUCTOR,_large: DigiKey: 490-5114-1-ND; DigiReel: 490-5114-6-ND; Family: passive; Index PN: 1149; Install: Y; Lead Style: SMT; MFG: Murata; P/D_NUM: LQM2HPN2R2MG0L; Part Number: LQM2HPN2R2MG0L; Part Specific: INDUCTOR 2.2UH 20% 1300MA 1008; Type: inductor; VENDOR: Murata
L502 = PAS,INDUCTOR,_large: Family: passive; Install: Y; Lead Style: SMT; MFG: CoilCraft; P/D_NUM: XFL4020-222MEB; Part Number: XFL4020-222MEB; Part Specific: Fixed Inductors 2.2uH 20% 8A; Type: inductor; VENDOR: Coilcraft
R38 R594 = PAS,R,large: DigiKey: 311-180KLRCT-ND; DigiReel: 311-180KLRDKR-ND; Family: passive; Index PN: 1179; Lead Style: SMT; MFG: Yageo; P/D_NUM: RC0402FR-07180KL; Part Number: RC0402FR-07180KL; Part Specific: RES SMD 180K OHM 1% 1/16W 0402; TOLERANCE: 1%; Type: resistor; VENDOR: Yageo; VPC: 1/16W
R39 = PAS,R,large: DigiKey: P226KLCT-ND; DigiReel: P226KLDKR-ND; Family: passive; Lead Style: SMT; MFG: Panasonic; P/D_NUM: ERJ-2RKF2263X; Part Number: ERJ-2RKF2263X; Part Specific: RES SMD 226K OHM 1% 1/10W 0402; TOLERANCE: 1%; Type: resistor; VENDOR: Panasonic; VPC: 1/10W
R586 = PAS,R,large: DigiKey: P240LCT-ND; DigiReel: P240LDKR-ND; Family: passive; Index PN: 1303; Lead Style: SMT; MFG: Panasonic; P/D_NUM: ERJ-2RKF2400X; Part Number: ERJ-2RKF2400X; Part Specific: RES SMD 240 OHM 1% 1/10W 0402; TOLERANCE: 1%; Type: resistor; VENDOR: Panasonic; VPC: 1/16W
R587 = PAS,R,large: DigiKey: P3.09KLCT-ND; DigiReel: P3.09KLDKR-ND; Family: passive; Index PN: 1307; Lead Style: SMT; MFG: Panasonic; P/D_NUM: ERJ-2RKF3091X; Part Number: ERJ-2RKF3091X; Part Specific: RES SMD 3.09K OHM 1% 1/10W 0402; Type: resistor; VENDOR: Panasonic; VPC: 1/16W
R589 R590 = PAS,R,large: DigiKey: 541-100KLCT-ND; DigiReel: 541-100KLDKR-ND; Family: passive; Index PN: 712; Lead Style: SMT; MFG: Vishay/Dale; Material: chip; P/D_NUM: CRCW0402100KFKED; Part Number: CRCW0402100KFKED; Part Specific: RES 100K OHM 1/10W 1% 0402 SMD; Power: 1/16W; TOLERANCE: 1%; Type: resistor; VPC: 1/16W; Vendor: Vishay/Dale
R591 = PAS,R,large: DigiKey: P10.0KLCT-ND; DigiReel: P10.0KLDKR-ND; Family: passive; Index PN: 680; Install: Y; Lead Style: SMT; MFG: Panasonic; Material: chip; P/D_NUM: ERJ-2RKF1002X; Part Number: ERJ-2RKF1002X; Part Specific: RES SMD 10K OHM 1% 1/10W 0402; Power: 1/16W; TOLERANCE: 1%; Type: resistor; VPC: 1/16W; Vendor: Panasonic
R595 = PAS,R,large: DigiKey: P360KLCT-ND; DigiReel: P360KLDKR-ND; Family: passive; Lead Style: SMT; MFG: Panasonic; P/D_NUM: ERJ-2RKF3603X; Part Number: ERJ-2RKF3603X; Part Specific: RES SMD 360K OHM 1% 1/10W 0402; TOLERANCE: 1%; Type: resistor; VENDOR: Panasonic; VPC: 1/10W
U4 U8 U11 U14 = PWR,SW,TPS22929DDBV: DigiKey: 296-30174-1-ND; DigiReel: 296-30174-6-ND; Family: power; Index PN: 1309; Lead Style: SMT; MFG: Texas Instruments; Part Specific: IC LOAD SWITCH SOT23-6; Type: switch; Vendor: Texas Instruments
U16 = LOG,AND,OPENDRN,Tiny_Logic: DigiKey: 296-29202-1-ND; DigiReel: 296-29202-6-ND; Index PN: 1094; Lead Style: SMT; MFG: Texas Instruments; Part Specific: IC GATE AND SGL 2INP; Type: and; Vendor: Texas Instruments
U17 = LOG,AND,Tiny_Logic: DigiKey: 296-19074-6-ND; DigiReel: 296-41491-6-ND; Index PN: 1378; Lead Style: SMT; MFG: Texas Instruments; P/D_NUM: SN74AUP1G08DBVR; Part Number: SN74AUP1G08DBVR; Part Specific: AND Gate IC 1 Channel SOT-23-5; Type: and; Vendor: Texas Instruments
U19 = PWR,REG,TPS62240,TSOT23_DDC: DigiKey: 296-41858-1-ND; DigiReel: 296-41858-6-ND; Install: Y; Lead Style: SMT; MFG: Texas Instruments; P/D_NUM: TPS62240DDCR; Part Number: TPS62240DDCR; Part Specific: IC REG BUCK ADJ 0.3A SYNC TSOT23; Pin Cnt: 5; Type: regulator; Vendor: Texas Instruments
U506 = PWR,REG,TPS56x209,SOT23_DDC: DigiKey: 296-37302-2-ND; DigiReel: 296-37302-6-ND; Family: power; Index PN: 1305; Lead Style: SMT; MFG: Texas Instruments; Part Specific: IC REG BUCK ADJ 2A SYNC SOT-23-6; Type: regulator; Vendor: Texas Instruments
U511 = PWR,REG,TPS62260,TSOT23_DDC: DigiKey: 296-22469-1-ND; DigiReel: 296-22469-6-ND; Family: power; Index PN: 1147; Install: Y; Lead Style: SMT; MFG: Texas Instruments; Part Specific: IC REG BUCK SYNC ADJ TSOT23-5; Type: regulator; Vendor: Texas Instruments
C508 = PAS,CAP,NP,large: DigiKey: 445-4999-1-ND; DigiReel: 445-4999-6-ND; Family: passive; Index PN: 915; Lead Style: SMT; MFG: TDK; Material: x5r; P/D_NUM: C1005X5R0J225M050BC; Part Number: C1005X5R0J225M050BC; Part Specific: CAP CER 2.2UF 6.3V X5R 0402; TOLERANCE: 10%; Type: capacitor; VENDOR: TDK; VPC: 6.3V; Voltage: 6.3V
C545 C546 = PAS,CAP,NP,large_2: DigiKey: 399-8984-2-ND; DigiReel: 399-8984-6-ND; Family: passive; Install: DNI; Lead Style: SMT; MFG: KEMET; P/D_NUM: C0603C102K8RACTU; Part Number: C0603C102K8RACTU; Part Specific: CAP CER 1000PF 10V X7R 0603; TOLERANCE: 20%; Type: capacitor; VENDOR: TDK; VPC: 10V; Voltage: 10V
J1 = EM,CONN,4P+2G,1R,FLEX,2X_0: DigiKey: WM1386CT-ND; DigiReel: WM1386DKR-ND; Family: electro/mechanical; Index PN: 1371; Lead Style: SMT; MFG: Molex; Part Specific: CONN FFC FPC 4POS 0.50MM R/A; Pin Cnt: 4; Pin Spacing: 0.5mm; Row Cnt: 1; Type: connector; Vendor: Molex
R10 R11 R524 = PAS,R,large: DigiKey: P1.00KLCT-ND; DigiReel: P1.00KLDKR-ND; Family: passive; Index PN: 684; Install: Y; Lead Style: SMT; MFG: Panasonic; Material: chip; P/D_NUM: ERJ-2RKF1001X; Part Number: ERJ-2RKF1001X; Part Specific: RES 1.00K OHM 1/10W 1% 0402 SMD; Power: 1/16W; TOLERANCE: 1%; Type: resistor; VENDOR: Panasonic; VPC: 1/16W
R506 R518 = PAS,R,large: DigiKey: P.47AJCT-ND; DigiReel: P.47AJDKR-ND; Family: passive; Lead Style: SMT; MFG: Panasonic; Material: chip; P/D_NUM: ERJ-3RQFR47V; Part Number: ERJ-3RQFR47V; Part Specific: RES 0.47 OHM 1% 1/10W 0603; Power: 1/10W; TOLERANCE: 1%; Type: resistor; VENDOR: Panasonic; VPC: 1/10W
R521 R522 = PAS,R,large: DigiKey: P1.00KLCT-ND; DigiReel: P1.00KLDKR-ND; Family: passive; Index PN: 684; Install: DNI; Lead Style: SMT; MFG: Panasonic; Material: chip; P/D_NUM: ERJ-2RKF1001X; Part Number: ERJ-2RKF1001X; Part Specific: RES 1.00K OHM 1/10W 1% 0402 SMD; Power: 1/16W; TOLERANCE: 1%; Type: resistor; VENDOR: Panasonic; VPC: 1/16W
U5 = PROC,DRV8833PWR_3: DigiKey: 296-40078-1-ND; DigiReel: 296-40078-6-ND; MFG: Texas Instruments; P/D_NUM: DRV8833CPWPR; Part Specific: IC MOTOR DRIVER PAR; Part_Number: DRV8833CPWPR; Type: Motor Driver; Vendor: Texas Instruments
U6 = LOG,XCVR,74x4T774: DigiKey: 296-24739-1-ND; DigiReel: 296-24739-6-ND; Family: logic; Index PN: 871; Lead Style: SMT; MFG: Texas Instruments; Part Specific: IC BUS TRANSCVR 4BIT DL 16TSSOP; Type: transceiver; Vendor: Texas Instruments

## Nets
GND: C8.2(N) C9.2(N) C10.2(N) C11.2(N) C12.2(N) C13.2(N) C14.2(N) C15.2(N) C16.1(P) C17.2(N) C19.2(N) C20.2(N) C21.2(N) C28.2(N) C29.2(N) C32.2(N) C500.1(P) C502.2(N) C503.2(N) C504.2(N) C505.2(N) C506.1(P) C507.1(P) C508.1(P) C509.2(N) C510.2(N) C511.2(N) C512.2(N) C513.2(N) C514.2(N) C515.2(N) C516.2(N) C517.2(N) C518.2(N) C519.2(N) C520.2(N) C521.2(N) C522.2(N) C523.2(N) C524.2(N) C527.2(N) C529.2(N) C530.2(N) C531.1(P) C532.2(N) C533.2(N) C534.2(N) C535.2(N) C537.2(N) C538.1(P) C539.2(N) C540.2(N) C541.2(N) C542.2(N) C543.2(N) C544.2(N) C550.1(P) C552.2(N) C553.2(N) C554.2(N) C555.2(N) C556.2(N) C557.2(N) C558.2(N) C566.2(N) C567.2(N) C568.2(N) C569.2(N) C570.2(N) C571.2(N) C572.2(N) C573.2(N) C574.2(N) C575.2(N) C576.2(N) C577.2(N) C578.2(N) C589.2(N) C590.2(N) C591.2(N) C592.2(N) C593.2(N) C594.2(N) C595.2(N) C596.2(N) C597.2(N) C598.2(N) C599.2(N) C600.2(N) C601.2(N) C611.2(N) C613.2(N) C616.2(N) C617.2(N) C618.2(N) C620.2(N) C621.2(N) C623.2(N) C624.2(N) C625.2(N) C629.1(P) C630.2(N) C631.2(N) C632.2(N) C633.2(N) C634.2(N) C635.2(N) C636.2(N) C637.2(N) C638.2(N) C639.2(N) C640.2(N) C642.2(N) C643.2(N) C644.2(N) C648.1(P) C649.2(N) C650.2(N) C651.2(N) C652.2(N) C653.2(N) C656.2(N) C658.1(P) C659.1(P) F500.2(N2) J1.5(P5) J1.6(P6) J3.3 J3.6 J3.9 J3.12 J3.15 J3.18 J3.21 J3.24 J3.27 J3.30 J3.33 J3.36 J3.37 J3.38 J3.39 J3.40 J3.41 J3.42(GND) J3.43(GND) J3.44(GND) J3.45(GND) J3.46(GND) J3.47(GND) J3.48(GND) J3.49(GND) J3.50(GND) J3.51(GND) R10.1(N1) R18.2(N2) R38.1(N1) R503.1(N1) R506.2(N2) R513.1(N1) R514.1(N1) R518.2(N2) R528.1(N1) R558.2(N2) R559.2(N2) R588.1(N1) R589.1(N1) R590.1(N1) R594.1(N1) U4.2(GND) U4.5(GND) U5.13(GND) U5.17(PAD) U6.10(GND) U7.5(AGND1) U7.12(PGNDR) U7.20(GND) U7.23(PGNDCM) U7.45(PGNDL_1) U7.46(PGNDL_2) U7.PAD(THERMAL) U8.2(GND) U8.5(GND) U9.4(GND) U11.2(GND) U11.5(GND) U12.A5(GND) U12.A15(GND) U12.AA5(GND) U12.AA15(GND) U12.AB8(GND) U12.AB18(GND) U12.B8(GND) U12.B18(GND) U12.C1(GND) U12.C11(GND) U12.C21(GND) U12.D4(GND) U12.D14(GND) U12.E7(GND) U12.E17(GND) U12.F10(GND) U12.F20(GND) U12.G3(GND) U12.H6(GND) U12.H8(GND) U12.H12(GND) U12.H14(GND) U12.H16(GND) U12.J9(GND) U12.J11(GND) U12.J13(GND) U12.J19(GND) U12.K2(GND) U12.K8(GND) U12.K10(GND) U12.K14(GND) U12.K22(GND) U12.L5(GND) U12.L9(GND) U12.L13(GND) U12.L15(GND) U12.M8(GND) U12.M10(GND) U12.M14(GND) U12.M18(GND) U12.N1(GND) U12.N9(GND) U12.N13(GND) U12.N21(GND) U12.P4(GND) U12.P8(GND) U12.P10(GND) U12.P12(GND) U12.P14(GND) U12.R9(GND) U12.R11(GND) U12.R13(GND) U12.R17(GND) U12.T20(GND) U12.U3(GND) U12.U13(GND) U12.V6(GND) U12.V16(GND) U12.W9(GND) U12.W19(GND) U12.Y2(GND) U12.Y12(GND) U12.Y22(GND) U14.2(GND) U14.5(GND) U16.3(GND) U17.3(GND) U19.2(GND) U506.1(GND) U511.2(GND) UDPP.C4(VSS) UDPP.C6(VSS) UDPP.C8(VSS) UDPP.C10(HWTEST_EN) UDPP.D6(VSS) UDPP.D8(VSS) UDPP.D10(VSS) UDPP.E4(VSS) UDPP.E13(VSS) UDPP.F4(VSS) UDPP.G4(VSS) UDPP.G12(VSS) UDPP.G13(VSS) UDPP.H4(VSS) UDPP.H12(VSS) UDPP.J3(VSS) UDPP.J13(VSS) UDPP.K4(VSS) UDPP.K12(VSS) UDPP.L3(VSS) UDPP.M4(VSS) UDPP.M5(VSS) UDPP.M8(VSS) UDPP.M12(VSS) UOSC.2(GND) ; also on sheet 9 10 11 12 13 14
P5V: C8.1(P) C9.1(P) C16.2(N) C504.1(P) C505.1(P) C530.1(P) C535.1(P) C550.2(N) C629.2(N) C648.2(N) C652.1(P) U7.1(VINL) U7.2(VINL) U7.10(VINR) U7.18(VINA) U7.25(VINC) U19.1(VIN) U506.3(VIN) U511.1(VIN) ; also on sheet 13
V2V5: C532.1(P) U7.19(V2V5)
V6V: C500.2(N) U7.35(V6V)
VCCDDR: C19.1(P) C20.1(P) C28.1(P) C29.1(P) C34.1(P) C566.1(P) C567.1(P) C611.1(P) L4.2 R39.2(N2) U12.E2(VCCO_DDR_502) U12.F5(VCCO_DDR_502) U12.H1(VCCO_DDR_502) U12.J4(VCCO_DDR_502) U12.K7(VCCO_DDR_502) U12.M3(VCCO_DDR_502) U12.N6(VCCO_DDR_502) U12.R2(VCCO_DDR_502) U12.V1(VCCO_DDR_502) ; also on sheet 9
VCCINT: C13.1(P) C554.1(P) C570.1(P) C589.1(P) C592.1(P) C593.1(P) C594.1(P) C595.1(P) C596.1(P) C613.1(P) C617.1(P) C630.1(P) C637.1(P) C640.1(P) C651.1(P) C658.2(N) C659.2(N) L502.1 R587.2(N2) U12.G8(VCCPINT) U12.H9(VCCPINT) U12.H11(VCCBRAM) U12.J8(VCCPINT) U12.J10(VCCBRAM) U12.J12(VCCINT) U12.J14(VCCINT) U12.K13(VCCINT) U12.L8(VCCPINT) U12.L14(VCCINT) U12.M13(VCCINT) U12.N8(VCCPINT) U12.N14(VCCINT) U12.P13(VCCINT) U12.R8(VCCPINT) U12.R14(VCCINT)
VCCINT_EN: C653.1(P) R586.2(N2) U506.5(EN) U511.3(EN)
VCCPLL: C633.1(P) C635.1(P) F502.1(N1) U12.H10(VCCPLL)
VDD_PLL: C525.2(N) C526.1(P) F501.1(N1) UDPP.H2(VDD_PLLM) UDPP.J2(VDD_PLLD)
VINT: C508.2(N) U5.14(VINT)
VINTF: C21.1(P) C575.1(P) C597.1(P) C598.1(P) C599.1(P) C600.1(P) C601.1(P) C620.1(P) U11.1(VOUT) U12.K17(VCCO_34) U12.L20(VCCO_34) U12.N16(VCCO_34) U12.P19(VCCO_34) U12.R22(VCCO_34) U12.T15(VCCO_34) ; also on sheet 10
VSS_PLL: C525.1(P) C526.2(N) F500.1(N1) UDPP.G3(VSS_PLLM) UDPP.H3(VSS_PLLD)
ACT_1DIR: R504.2(N2) U6.1(DIR1)
ACT_2DIR: R505.2(N2) U6.2(DIR2)
ACT_3DIR: R515.2(N2) U6.7(DIR3)
ACT_4DIR: R516.2(N2) U6.8(DIR4)
ACT_SYNC: TP6.1(P1) U12.R7(IO_0_13) UDPP.L15(GPIO_17)
AIN1: U5.16(AIN1) U6.14(B1)
AIN2: U5.15(AIN2) U6.13(B2)
AISEN: R506.1(N1) U5.3(AISEN)
BIN1: U5.9(BIN1) U6.12(B3)
BIN2: U5.10(BIN2) U6.11(B4)
BISEN: R518.1(N1) U5.6(BISEN)
BLU_CATHODE: J503.5 J503.6 U7.37(SW6)
CLK_48: U12.Y6(IO_L13P_T2_MRCC_13) ; also on sheet 11
CMP_OUT: U7.28(CMP_OUT) UDPP.A12(CMP_OUT)
Coil_A_N: J1.2(P2) R521.1(N1) U5.4(AOUT2)
Coil_A_P: C545.1(P) J1.1(P1) U5.2(AOUT1)
Coil_C_N: J1.4(P4) R522.1(N1) U5.5(BOUT2)
Coil_C_P: C546.1(P) J1.3(P3) U5.7(BOUT1)
DAC_DATA_PWM_P_1A: U6.3(A1) U12.W6(IO_L24P_T3_13)
DAC_DATA_PWM_P_1B: U6.4(A2) U12.W7(IO_L23N_T3_13)
DAC_DATA_PWM_P_2A: U6.5(A3) U12.AB7(IO_L17P_T2_13)
DAC_DATA_PWM_P_2B: U6.6(A4) U12.AA11(IO_L8P_T1_13)
DAC_EN: R10.2(N2) U4.3(ON) U12.U6(IO_L22P_T3_13)
DLPC_SPICLK: R6.2(N2) UDPP.A13(SPI0_CLK)
DLPC_SPICSZ0: R8.2(N2) UDPP.A14(SPI0_CSZ0)
DLPC_SPICSZ1: R9.2(N2) UDPP.C12(SPI0_CSZ1)
DLPC_SPIDOUT: R7.2(N2) UDPP.B13(SPI0_DOUT)
FPD0_An: J3.22 R614.1(N1) U12.A22(IO_L15N_T2_DQS_AD12N_3)
FPD0_Ap: J3.23 R614.2(N2) U12.A21(IO_L15P_T2_DQS_AD12P_3)
FPD0_Bn: J3.28 R612.1(N1) U12.A19(IO_L10N_T1_AD11N_35)
FPD0_Bp: J3.29 R612.2(N2) U12.A18(IO_L10P_T1_AD11P_35)
FPD0_CLKn: J3.25 R613.1(N1) U12.B20(IO_L13N_T2_MRCC_35)
FPD0_CLKp: J3.26 R613.2(N2) U12.B19(IO_L13P_T2_MRCC_35)
FPD0_Cn: J3.31 R611.1(N1) U12.A17(IO_L9N_T1_DQS_AD3N_35)
FPD0_Cp: J3.32 R611.2(N2) U12.A16(IO_L9P_T1_DQS_AD3P_35)
FPD0_Dn: J3.19 R615.1(N1) U12.B22(IO_L18N_T2_AD13N_35)
FPD0_Dp: J3.20 R615.2(N2) U12.B21(IO_L18P_T2_AD13P_35)
FPD0_En: J3.34 R610.1(N1) U12.B17(IO_L8N_T1_AD10N_35)
FPD0_Ep: J3.35 R610.2(N2) U12.B16(IO_L8P_T1_AD10P_35)
FPD1_An: J3.5 R622.1(N1) U12.C22(IO_L16N_T2_35)
FPD1_Ap: J3.4 R622.2(N2) U12.D22(IO_L16P_T2_35)
FPD1_Bn: J3.8 R621.1(N1) U12.D21(IO_L17N_T2_AD5N_35)
FPD1_Bp: J3.7 R621.2(N2) U12.E21(IO_L17P_T2_AD5P_35)
FPD1_CLKn: J3.14 R618.1(N1) U12.C19(IO_L12N_T1_MRCC_35)
FPD1_CLKp: J3.13 R618.2(N2) U12.D18(IO_L12P_T1_MRCC_35)
FPD1_Cn: J3.11 R620.1(N1) U12.C20(IO_L14N_T2_AD4N_SRCC_3)
FPD1_Cp: J3.10 R620.2(N2) U12.D20(IO_L14P_T2_AD4P_SRCC_3)
FPD1_Dn: J3.2 R624.1(N1) U12.E20(IO_L21N_T3_DQS_AD14N_3)
FPD1_Dp: J3.1 R624.2(N2) U12.E19(IO_L21P_T3_DQS_AD14P_3)
FPD1_En: J3.17 R616.1(N1) U12.D17(IO_L2N_T0_AD8N_35)
FPD1_Ep: J3.16 R616.2(N2) U12.D16(IO_L2P_T0_AD8P_35)
FPGA_P1P8V: C12.1(P) C14.1(P) C506.2(N) C552.1(P) C553.1(P) C555.1(P) C556.1(P) C557.1(P) C558.1(P) C568.1(P) C569.1(P) C572.1(P) C573.1(P) C574.1(P) C576.1(P) C577.1(P) C578.1(P) C616.1(P) C632.1(P) C634.1(P) C636.1(P) C638.1(P) C639.1(P) R504.1(N1) R505.1(N1) R515.1(N1) R516.1(N1) U6.16(VCCA) U8.1(VOUT) U12.A10(VCCO_MIO1_501) U12.AA10(VCCO_13) U12.AA20(VCCO_33) U12.AB3(VCCO_13) U12.AB13(VCCO_33) U12.B3(VCCO_MIO0_500) U12.B13(VCCO_MIO1_501) U12.C6(VCCO_MIO0_500) U12.D9(VCCO_MIO1_501) U12.E12(VCCO_MIO1_501) U12.R12(VCCO_0) U12.T5(VCCO_13) U12.U8(VCCO_13) U12.U18(VCCO_33) U12.V11(VCCO_13) U12.V21(VCCO_33) U12.W4(VCCO_13) U12.W14(VCCO_33) U12.Y7(VCCO_13) U12.Y17(VCCO_33) ; also on sheet 11 12
FPGA_RDY: TP2.1(P1) U12.AA9(IO_L11P_T1_SRCC_13) UDPP.K14(GPIO_14) ; also on sheet 11
GPIO_1: R16.2(N2) R511.1(N1) UDPP.C15(GPIO_1)
GPIO_2: R501.2(N2) R502.1(N1) UDPP.D14(GPIO_2)
GPIO_3: R510.2(N2) R512.1(N1) UDPP.D15(GPIO_3)
GRN_CATHODE: J501.5 J501.6 U7.38(SW5)
I2C0_SCL: UDPP.N10(IIC0_SCL) ; also on sheet 10
I2C0_SDA: UDPP.N9(IIC0_SDA) ; also on sheet 10
I2C1_SCL: R525.2(N2) UDPP.R11(IIC1_SCL) ; also on sheet 12
I2C1_SDA: R526.2(N2) UDPP.R10(IIC1_SDA) ; also on sheet 12
INTZ: R509.2(N2) R590.2(N2) U7.6(INTz) U17.1(A) UDPP.C13(PARKZ)
JTAG_TRSTZ: R528.2(N2) UDPP.P11(JTAGTRSTZ)
L1: L1.2 U7.47(L1_1) U7.48(L1_2)
L2: L1.1 U7.43(L2_1) U7.44(L2_2)
LED_ANODE: C10.1(P) C11.1(P) C502.1(P) C503.1(P) J501.1 J501.2 J502.1 J502.2 J503.1 J503.2 TP4.1(P1) U7.41(VLED_1) U7.42(VLED_2)
LED_SEL_0: R514.2(N2) U7.31(LED_SEL0) UDPP.B15(LED_SEL_0)
LED_SEL_1: R503.2(N2) U7.34(LED_SEL1) UDPP.B14(LED_SEL_1)
mFLSH_MISO: R544.1(N1) U9.2(DO)
nFault: R519.1(N1) U5.8(nFAULT)
OEz: R513.2(N2) U6.9(~{OE})
OSC_OUT: R3.2(N2) UDPP.H1(PLL_REFCLK_I)
OSC_OUT_T: R3.1(N1) UOSC.3(OUT)
P1P0V_FB: R587.1(N1) R588.2(N2) U506.4(VFB)
P1P0V_SW: C641.1(P) L502.2 U506.2(SW)
P1P0V_VBST: C641.2(N) U506.6(VBST)
P1P1V: C17.1(P) C510.1(P) C512.1(P) C515.1(P) C517.1(P) C518.1(P) C520.1(P) C522.1(P) C523.1(P) C524.1(P) C539.1(P) C541.1(P) C543.1(P) F501.2(N2) L3.2 U7.29(VCORE) UDPP.C3(VDDLP12) UDPP.C5(VDD) UDPP.D3(VDD) UDPP.D5(VDD) UDPP.D7(VDD) UDPP.D9(VDD) UDPP.D12(VDD) UDPP.D13(VDD) UDPP.E3(VDD) UDPP.F13(VDD) UDPP.H13(VDD) UDPP.J4(VDD) UDPP.J12(VDD) UDPP.K3(VDD) UDPP.L4(VDD) UDPP.L12(VDD) UDPP.L13(VDD) UDPP.M6(VDD) UDPP.M9(VDD) UDPP.M10(VDD)
P1P8V: C511.1(P) C513.1(P) C516.1(P) C519.1(P) C521.1(P) C529.1(P) C531.2(N) C540.1(P) C542.1(P) C544.1(P) R2.1(N1) R502.2(N2) R509.1(N1) R511.2(N2) R512.2(N2) U7.21(LS_OUT) U7.32(VSPI) UDPP.C7(VCC) UDPP.C9(VCC) UDPP.D4(VCC) UDPP.E12(VCC) UDPP.F12(VCC) UDPP.K13(VCC) UDPP.M3(VCC_INTF) UDPP.M7(VCC_INTF) UDPP.M11(VCC) UDPP.N3(VCC_INTF) UDPP.N7(VCC_INTF) ; also on sheet 12 14
P1P8V_PRE: C32.1(P) C571.1(P) C590.1(P) C591.1(P) C631.1(P) C649.1(P) C650.1(P) C655.1(P) C656.1(P) F502.2(N2) L503.2 R595.2(N2) U12.K9(VCCPAUX) U12.L10(VCCAUX) U12.M9(VCCPAUX) U12.N10(VCCAUX) U12.P9(VCCPAUX) U12.P11(VCCAUX) U12.R10(VCCAUX) U12.T9(VCCPAUX) U16.2(B) ; also on sheet 11
P1P8V_PRE_FB: C655.2(N) R594.2(N2) R595.1(N1) U511.4(FB)
P1P8V_PRE_SW: L503.1 U511.5(SW)
P1P8V_SB: C514.1(P) R15.1(N1) R507.1(N1) R508.1(N1) R524.2(N2) R525.1(N1) R526.1(N1) U7.22(LS_IN) U8.4(VIN) U8.6(VIN) U9.3(~{WP}) U9.7(~{HOLD}) U9.8(VCC3) UDPP.D11(VCC_FLSH) ; also on sheet 10 11 13
P1P35V_FB: C34.2(N) R38.2(N2) R39.1(N1) U19.4(FB)
P1P35V_SW: L4.1 U19.5(SW)
P2P5V: C618.1(P) C621.1(P) C623.1(P) C624.1(P) C625.1(P) C642.1(P) C643.1(P) C644.1(P) U12.A20(VCCO_35) U12.C16(VCCO_35) U12.D19(VCCO_35) U12.E22(VCCO_35) U12.F15(VCCO_35) U12.G18(VCCO_35) U12.H21(VCCO_35) U14.1(VOUT) ; also on sheet 11 12
P2P5V_SB: R591.1(N1) U14.4(VIN) U14.6(VIN) U16.5(VCC) U17.5(VCC) ; also on sheet 13
P3P3V_SB: C507.2(N) C538.2(N) U4.4(VIN) U4.6(VIN) U6.15(VCCB) U11.4(VIN) U11.6(VIN) ; also on sheet 10 13
PHK1924_PWREN: R586.1(N1) U16.1(A) U17.4(Y)
PROJ_ON: R589.2(N2) U7.27(PROJ_ON) U17.2(B) UDPP.G14(GPIO_8) ; also on sheet 13
PWM_OUTPUT_SEL: R524.1(N1) U12.V8(IO_L2P_T0_13)
PWRON_SEQ: R591.2(N2) U8.3(ON) U11.3(ON) U14.3(ON) U16.4(Y) U19.3(EN)
RC_CoilA: C545.2(N) R521.2(N2)
RC_CoilC: C546.2(N) R522.2(N2)
RED_CATHODE: J502.5 J502.6 U7.39(SW4)
RESETZ: R15.2(N2) U7.4(RESETz) UDPP.C11(RESETZ)
RLIM: R18.1(N1) U7.36(RLIM_K) U7.40(RLIM)
SPI0_CLK: R6.1(N1) R558.1(N1) U9.6(CLK) ; also on sheet 10
SPI0_CSZ0: R8.1(N1) R507.2(N2) U9.1(~{CS}) ; also on sheet 10
SPI0_CSZ1: R9.1(N1) R508.2(N2)
SPI0_MISO: R544.2(N2) R559.1(N1) UDPP.B12(SPI0_DIN) ; also on sheet 10
SPI0_MOSI: R7.1(N1) U9.5(DIO) ; also on sheet 10
SPI1_CLK: R16.1(N1) U7.7(SPI_CLK)
SPI1_CSZ0: R510.1(N1) U7.8(SPI_CSZ)
SPI1_DIN: R17.2(N2) UDPP.C14(GPIO_0)
SPI1_DIN_T: R17.1(N1) U7.9(SPI_DOUT)
SPI1_DOUT: R501.1(N1) U7.3(SPI_DIN)
SUBFRAME1: UDPP.K15(GPIO_15) ; also on sheet 12
SUBFRAME2: UDPP.L14(GPIO_16) ; also on sheet 12
SWC: L3.1 U7.24(SWC)
SWN: D500.1(P1) L2.2 U7.11(SWN)
SWP: L2.1 U7.13(SWP)
VBIAS: C534.1(P) U7.15(VBIAS) ; also on sheet 14
VM_P3P3V: C509.1(P) C537.1(P) R11.2(N2) R519.2(N2) U4.1(VOUT) U5.12(VM)
VOFS: C533.1(P) U7.17(VOFS) ; also on sheet 14
VOSC: C527.1(P) R2.2(N2) UOSC.1(EN) UOSC.4(VDD)
VRST: C15.1(P) D500.2(P2) U7.14(CNTR_VRST) ; also on sheet 14
N21808478: R11.1(N1) U5.1(nSLEEP)

Not connected (* = marked no-connect by the designer): J501 3* 4*; J502 3* 4*; J503 3* 4*; U5 11(NC); U7 16(REF_VRST)* 26(PWM_IN) 30(SENS2) 33(SENS1); U12 AA4(IO_L18N_T2_13) AA6(IO_L14N_T2_SRCC_13)* AA7(IO_L14P_T2_SRCC_13)* AA8(IO_L11N_T1_SRCC_13)* AA12(IO_L7P_T1_13) AB1(IO_L15N_T2_DQS_13)* AB2(IO_L15P_T2_DQS_13)* AB4(IO_L16N_T2_13) AB5(IO_L16P_T2_13) AB6(IO_L17N_T2_13) AB9(IO_L9N_T1_DQS_13) AB10(IO_L9P_T1_DQS_13) AB11(IO_L8N_T1_13) AB12(IO_L7N_T1_13) B15(IO_L7N_T1_AD2N_35) C15(IO_L7P_T1_AD2P_35) C17(IO_L11P_T1_SRCC_35) C18(IO_L11N_T1_SRCC_35) D15(IO_L3N_T0_DQS_AD1N_35) E15(IO_L3P_T0_DQS_AD1P_35) E16(IO_L1N_T0_AD0N_35) E18(IO_L5N_T0_AD9N_35) F16(IO_L1P_T0_AD0P_35) F17(IO_L6N_T0_VREF_35) F18(IO_L5P_T0_AD9P_35) F19(IO_L20N_T3_AD6N_35) F21(IO_L23P_T3_35) F22(IO_L23N_T3_35) G15(IO_L4P_T0_35) G16(IO_L4N_T0_35) G17(IO_L6P_T0_35) G19(IO_L20P_T3_AD6P_35) G20(IO_L22P_T3_AD7P_35) G21(IO_L22N_T3_AD7N_35) G22(IO_L24N_T3_AD15N_35) H17(IO_0_35) H18(IO_25_35) H19(IO_L19P_T3_35) H20(IO_L19N_T3_VREF_35) H22(IO_L24P_T3_AD15P_35) R6(IO_L19P_T3_13)* T4(IO_L20P_T3_13) T6(IO_L19N_T3_VREF_13)* U4(IO_L20N_T3_13) U5(IO_L22N_T3_13) U7(IO_25_13) U9(IO_L6N_T0_VREF_13)* U10(IO_L6P_T0_13) U11(IO_L5N_T0_13)* U12(IO_L5P_T0_13)* V4(IO_L21N_T3_DQS_13) V5(IO_L21P_T3_DQS_13) V7(IO_L23P_T3_13) V9(IO_L1N_T0_13) V10(IO_L1P_T0_13) V12(IO_L4P_T0_13) W5(IO_L24N_T3_13) W8(IO_L2N_T0_13) W10(IO_L3N_T0_DQS_13) W11(IO_L3P_T0_DQS_13) W12(IO_L4N_T0_13) Y4(IO_L18P_T2_13) Y5(IO_L13N_T2_MRCC_13)* Y8(IO_L12N_T1_MRCC_13)* Y9(IO_L12P_T1_MRCC_13) Y10(IO_L10N_T1_13) Y11(IO_L10P_T1_13); UDPP A15(CMP_PWM) C1(NC9)* C2(NC10)* D1(NC7)* D2(NC8)* E1(NC1)* E2(NC2)* E14(GPIO_4) E15(GPIO_5) F1(NC5)* F2(NC6)* F3(NC11) F14(GPIO_6) F15(GPIO_7) G1(NC3)* G2(NC4)* G15(GPIO_9) H14(GPIO_10) H15(GPIO_11) J1(PLL_REFCLK_O) J14(GPIO_12) J15(GPIO_13) M13(JTAGTMS1) M14(GPIO_18) M15(GPIO_19) N11(JTAGTMS2) N12(JTAGTDO2) N13(JTAGTDO1) N14(TSTPT_6) N15(TSTPT_7) P12(JTAGTCK) P13(JTAGTDI) P14(TSTPT_4) P15(TSTPT_5) R12(TSTPT_0) R13(TSTPT_1) R14(TSTPT_2) R15(TSTPT_3)

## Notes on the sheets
sheet 1
- MASTER
- VOFS= 10.0V
- VBIAS= 18V
- VRST= -14V
sheet 2
- - SHUTDOWN WHEN FAST PARK DETECTED.
- - PROJ_ON GOING HIGH ENABLES POWER TO FPGA
- ACTUATOR
- PARALLEL OUT
- PARALLEL IN
- FPD-LINK
- LOAD SWITCHES FOR I/O POWER
- 1.0V out use 3.09k
- 600mA Out
- 300mA Out
sheet 4
- DLPC3436 Clock, Reset, SPI and Flash Memory
sheet 5
- Revisions:
  E.0: Engineering Release
  A:
  Changed resistor value for R628 from 20k to  1k reduction of IR drop
  Changed resistor value for R626 from 100k to 1k reduction of IR drop
  Add 0.01uF caps C666, C667, C668, C669 for Raspberry PI drive strength
sheet 6
- The DSI Port is not supported by the
  DLPC3436. Inputs are left unconnected
  per datasheet recommendation.
- POWER - DLPC3436
sheet 7
- BANK 13
- Note: The actuator driver design is only applicable for the actuator used with the DLPDLCR230NPEVM. Please
  contact your actuator manufacture for the appropriate driver solution.
- VCCO_13 = P1P8V
- ACTUATOR DRIVER
sheet 8
- TB2
- TA2
- TB2
- TC2
- TCLK2
- TD1
- TA1
- TCLK1
- TB1
- TC1
- VCCO_35 = P2P5V
